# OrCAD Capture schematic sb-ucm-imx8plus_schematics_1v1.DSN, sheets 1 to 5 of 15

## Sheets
1 11. MIPI-CSI2 Connector, GMSL: size A2; title: SB-UCM-iMX8PLUS    11. MIPI-CSI2, GMSL Deserializer; rev: 1.1; note: 8000168001
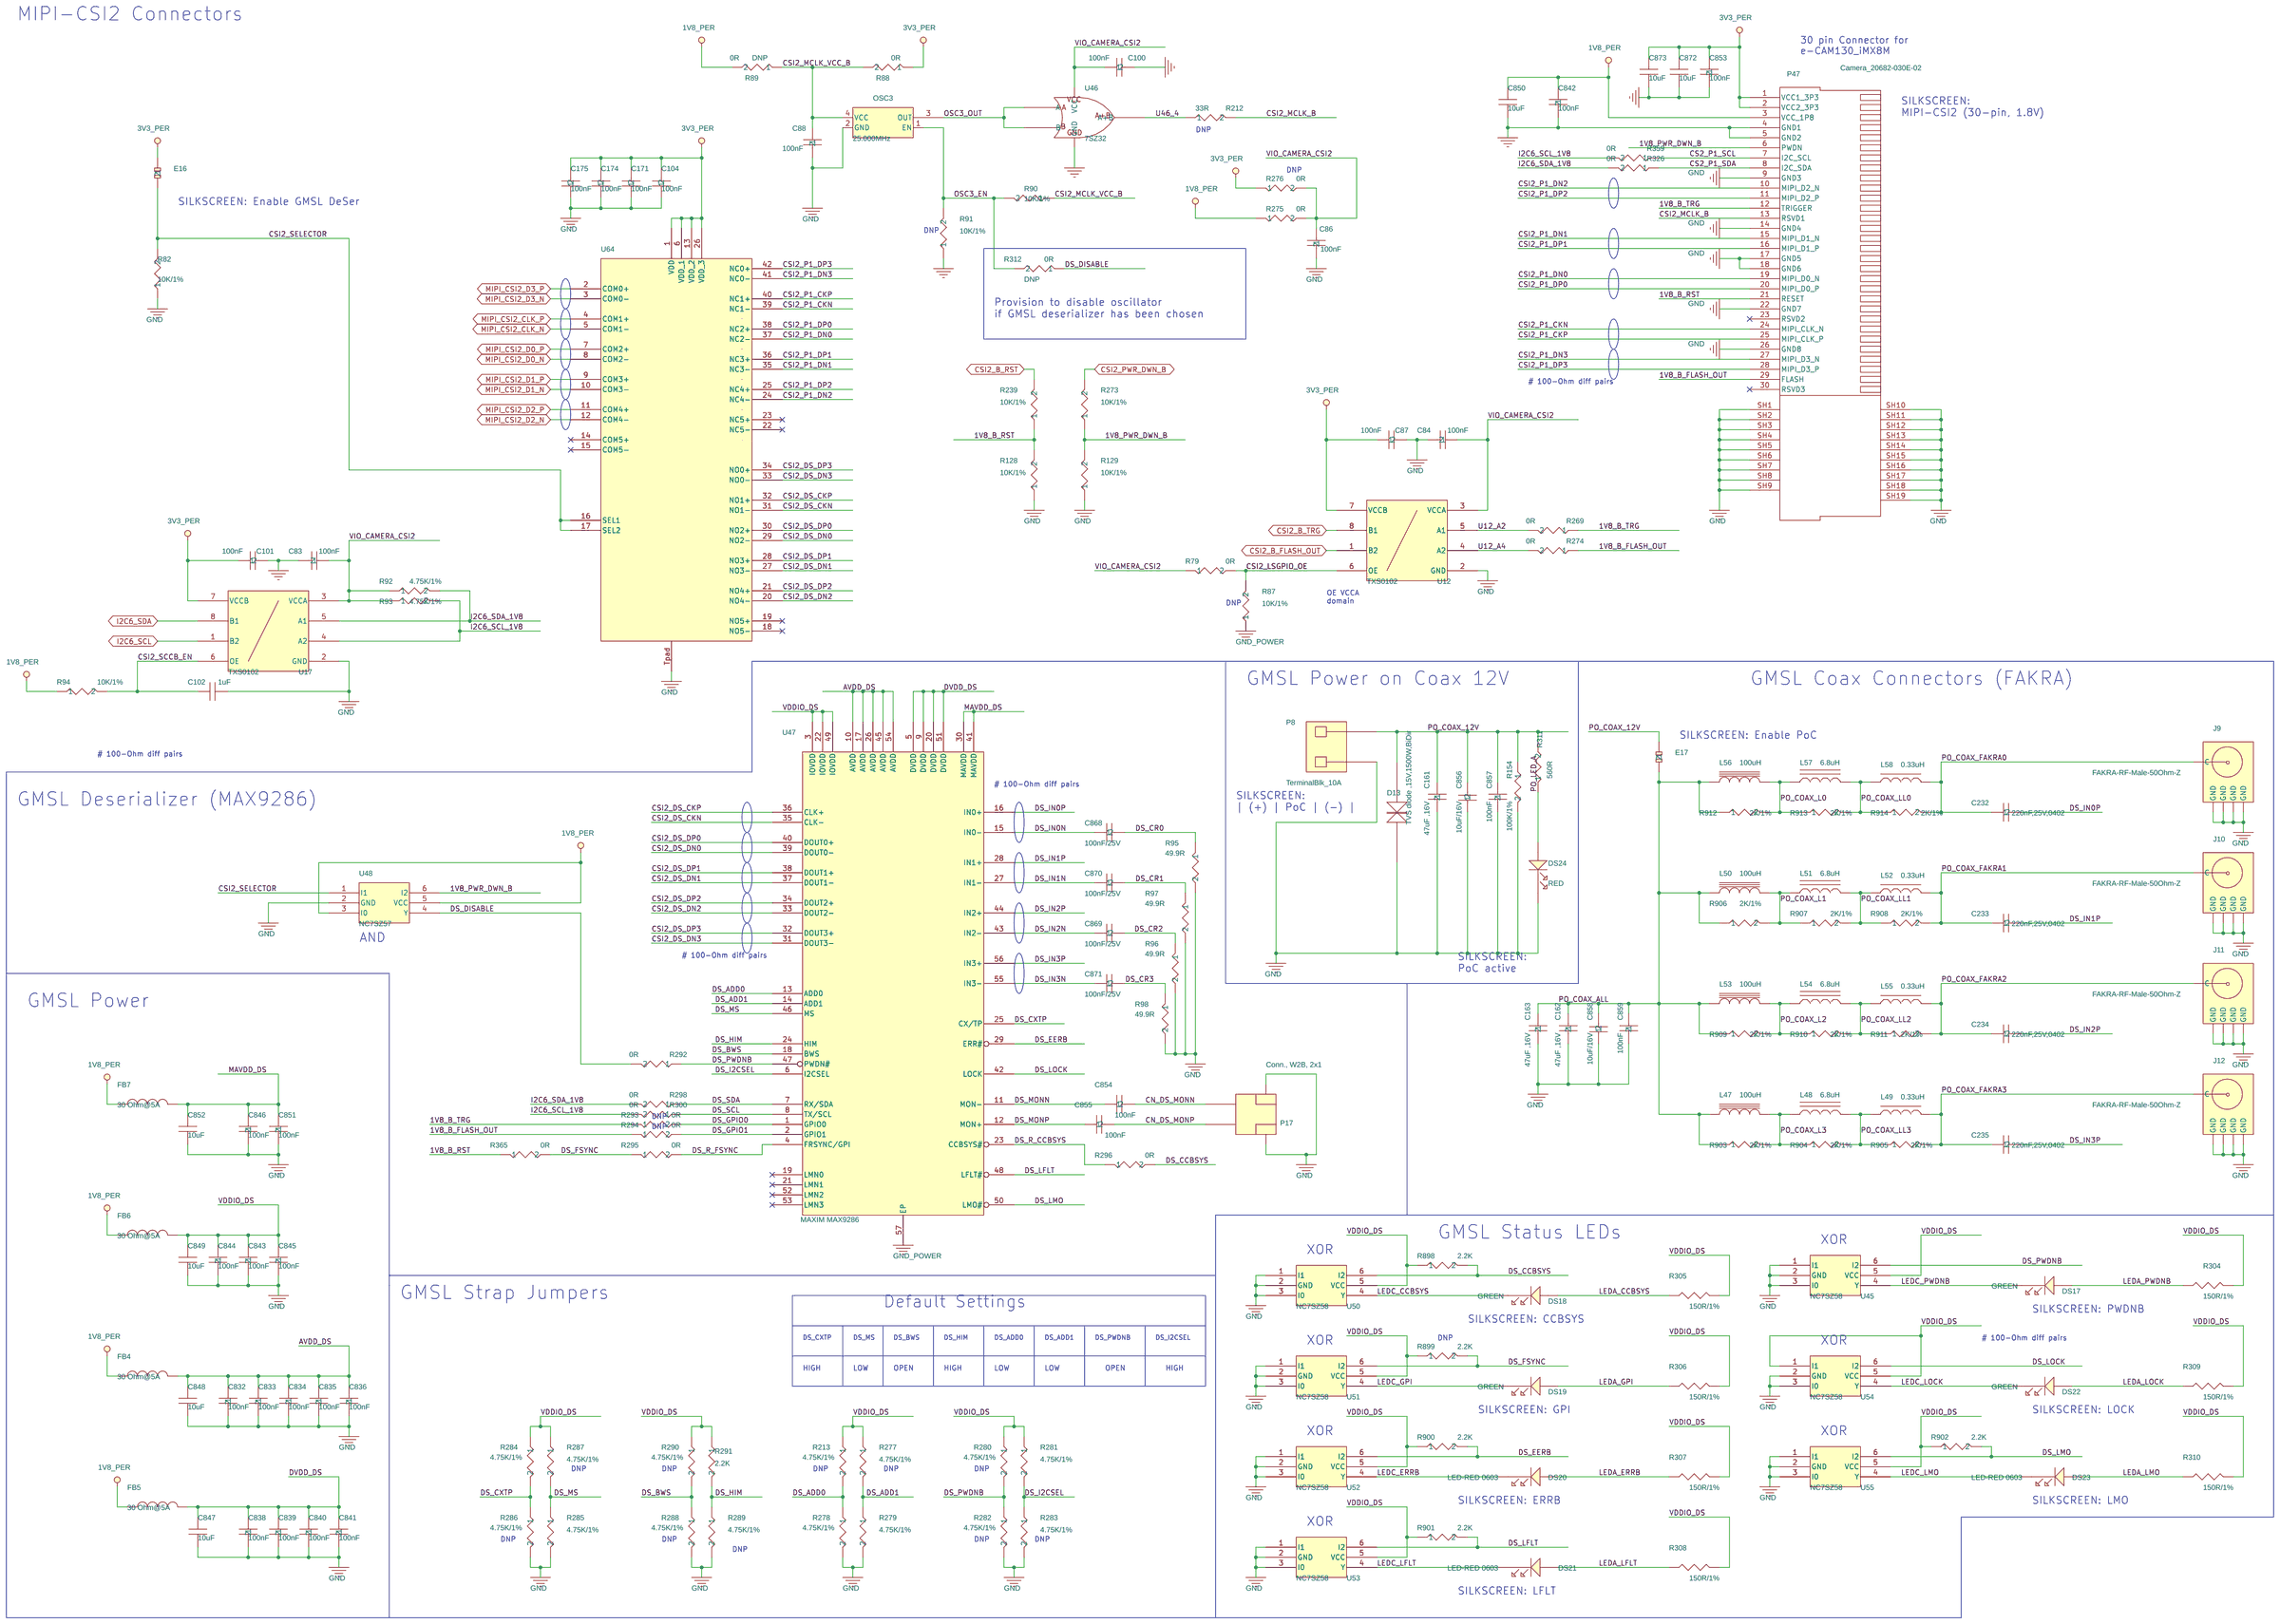
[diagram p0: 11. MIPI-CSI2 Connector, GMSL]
2 10. MIPI-CSI1 Connectors: size A3; title: SB-UCM-iMX8PLUS    10. MIPI-CSI1 Connectors
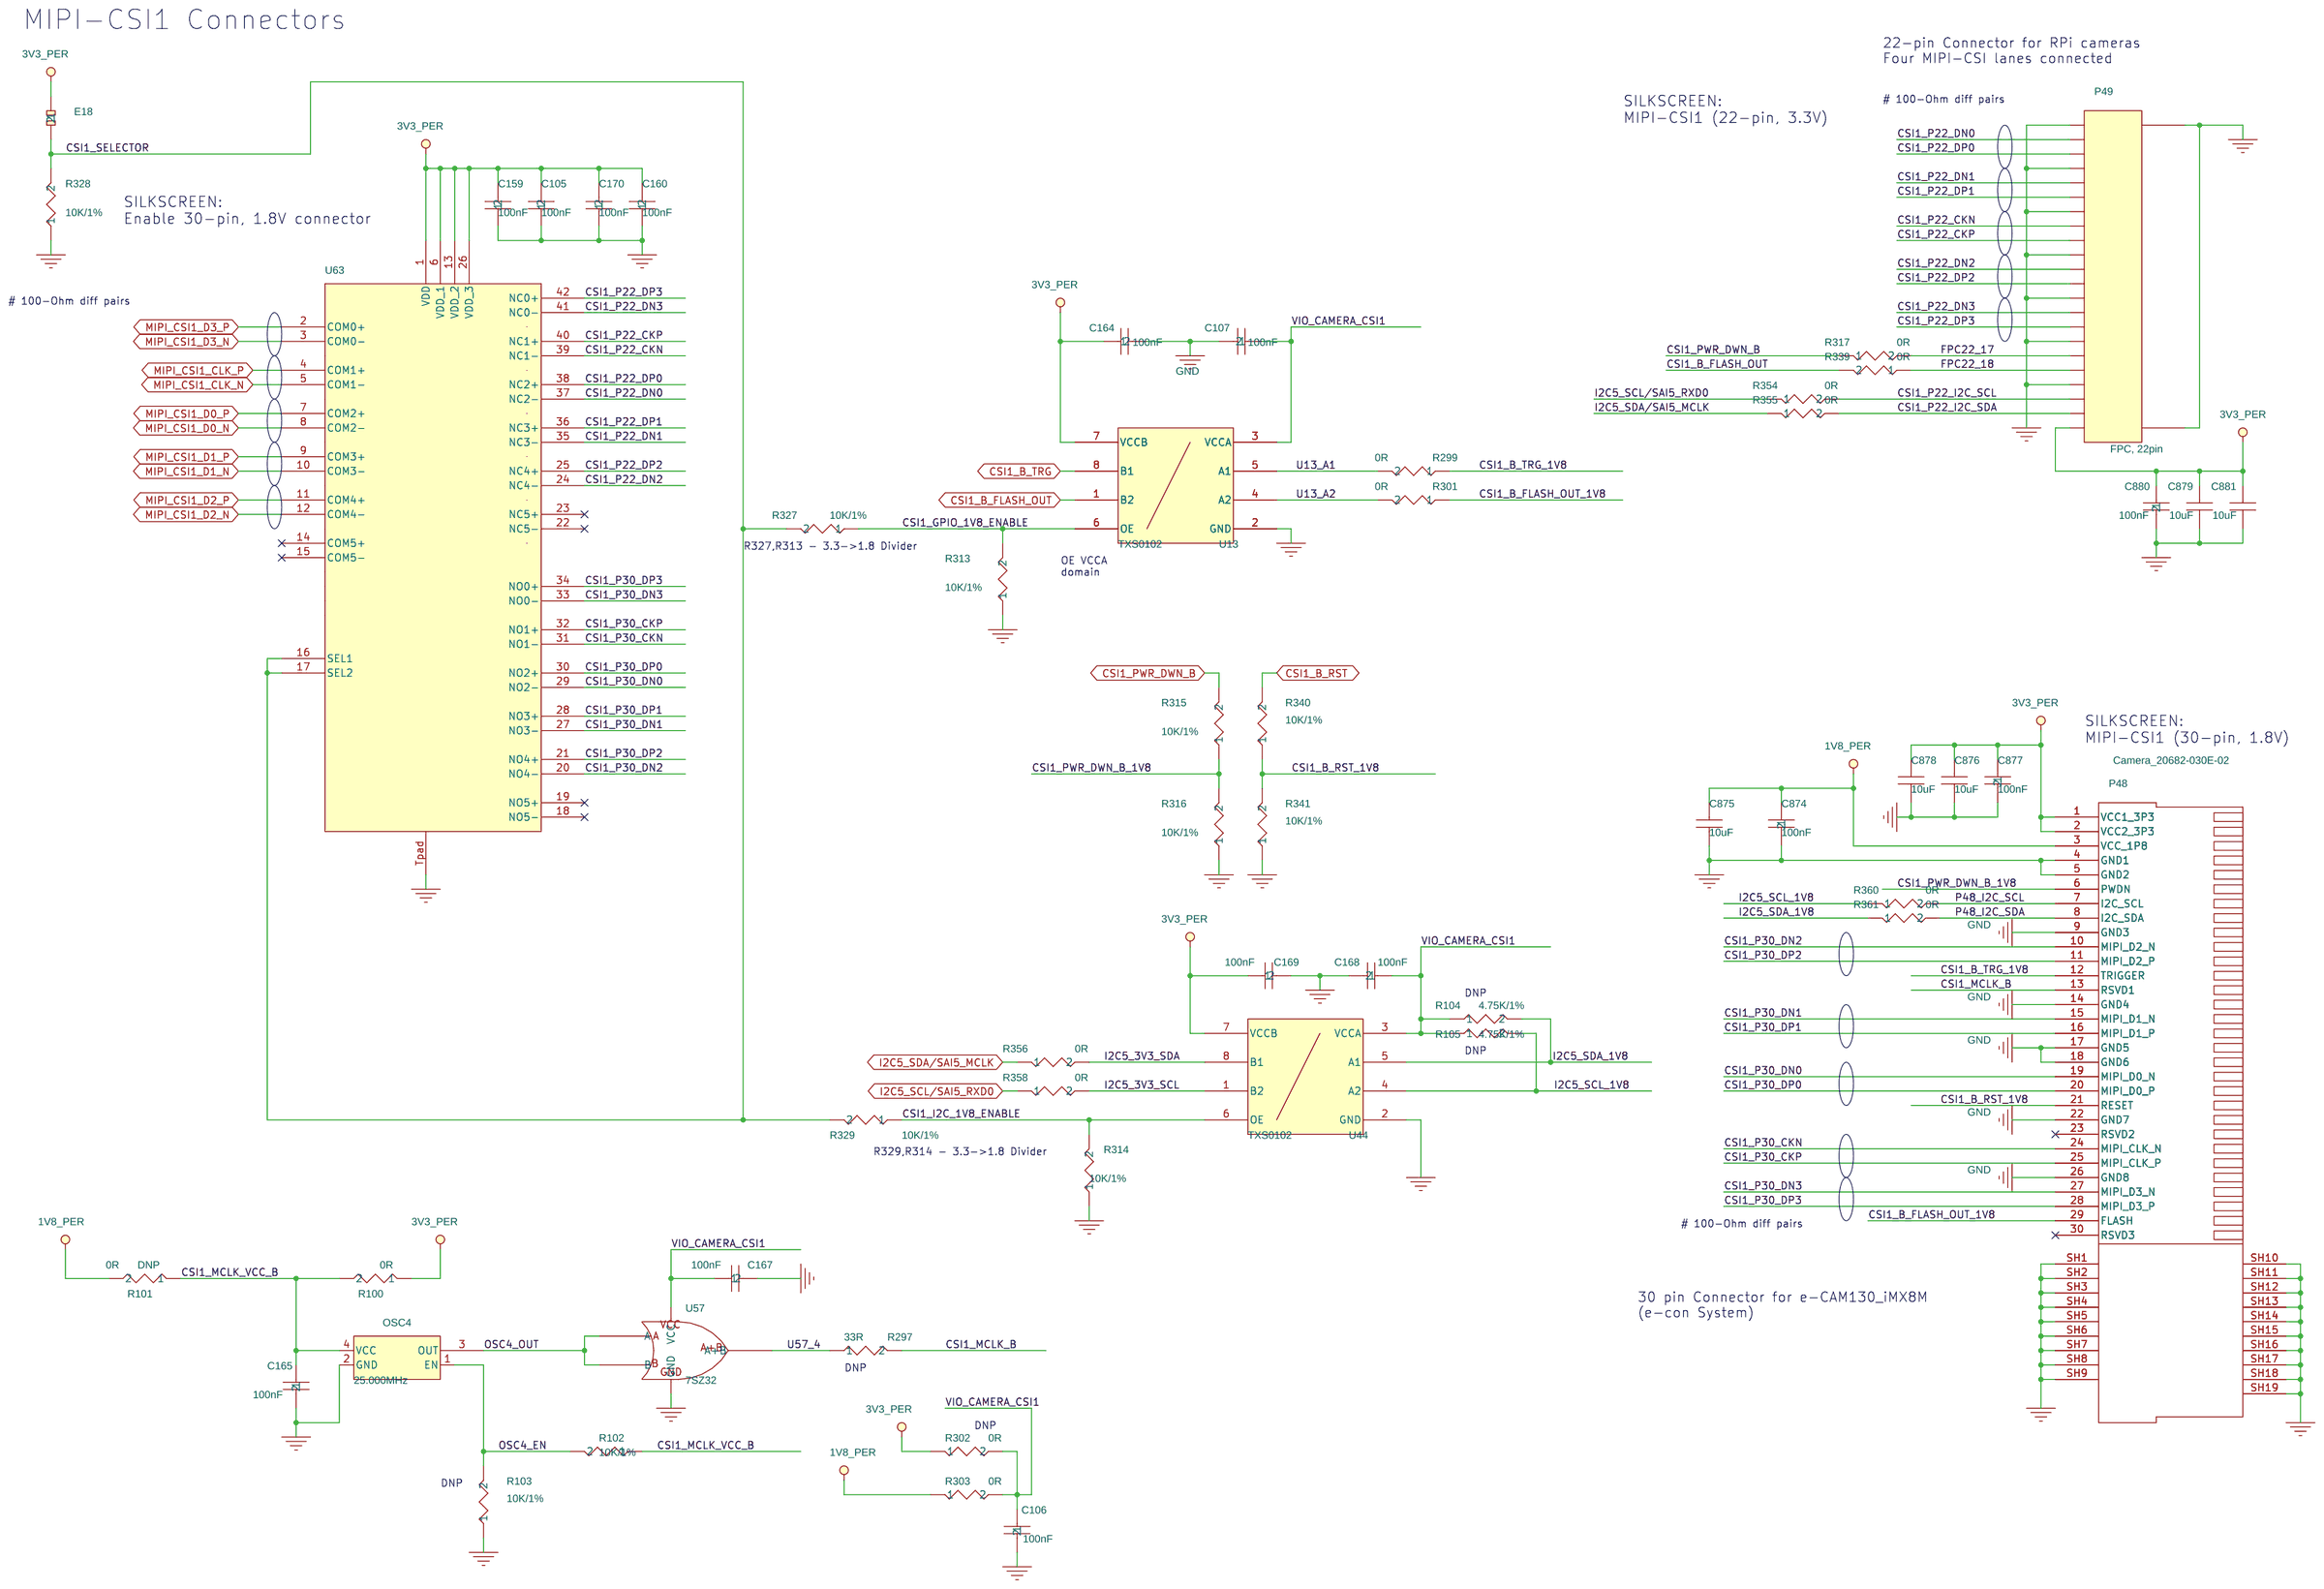
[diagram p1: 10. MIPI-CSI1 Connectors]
3 09. HDMI, eARC: size A3; title: SB-UCM-iMX8PLUS   09. HDMI, eARC
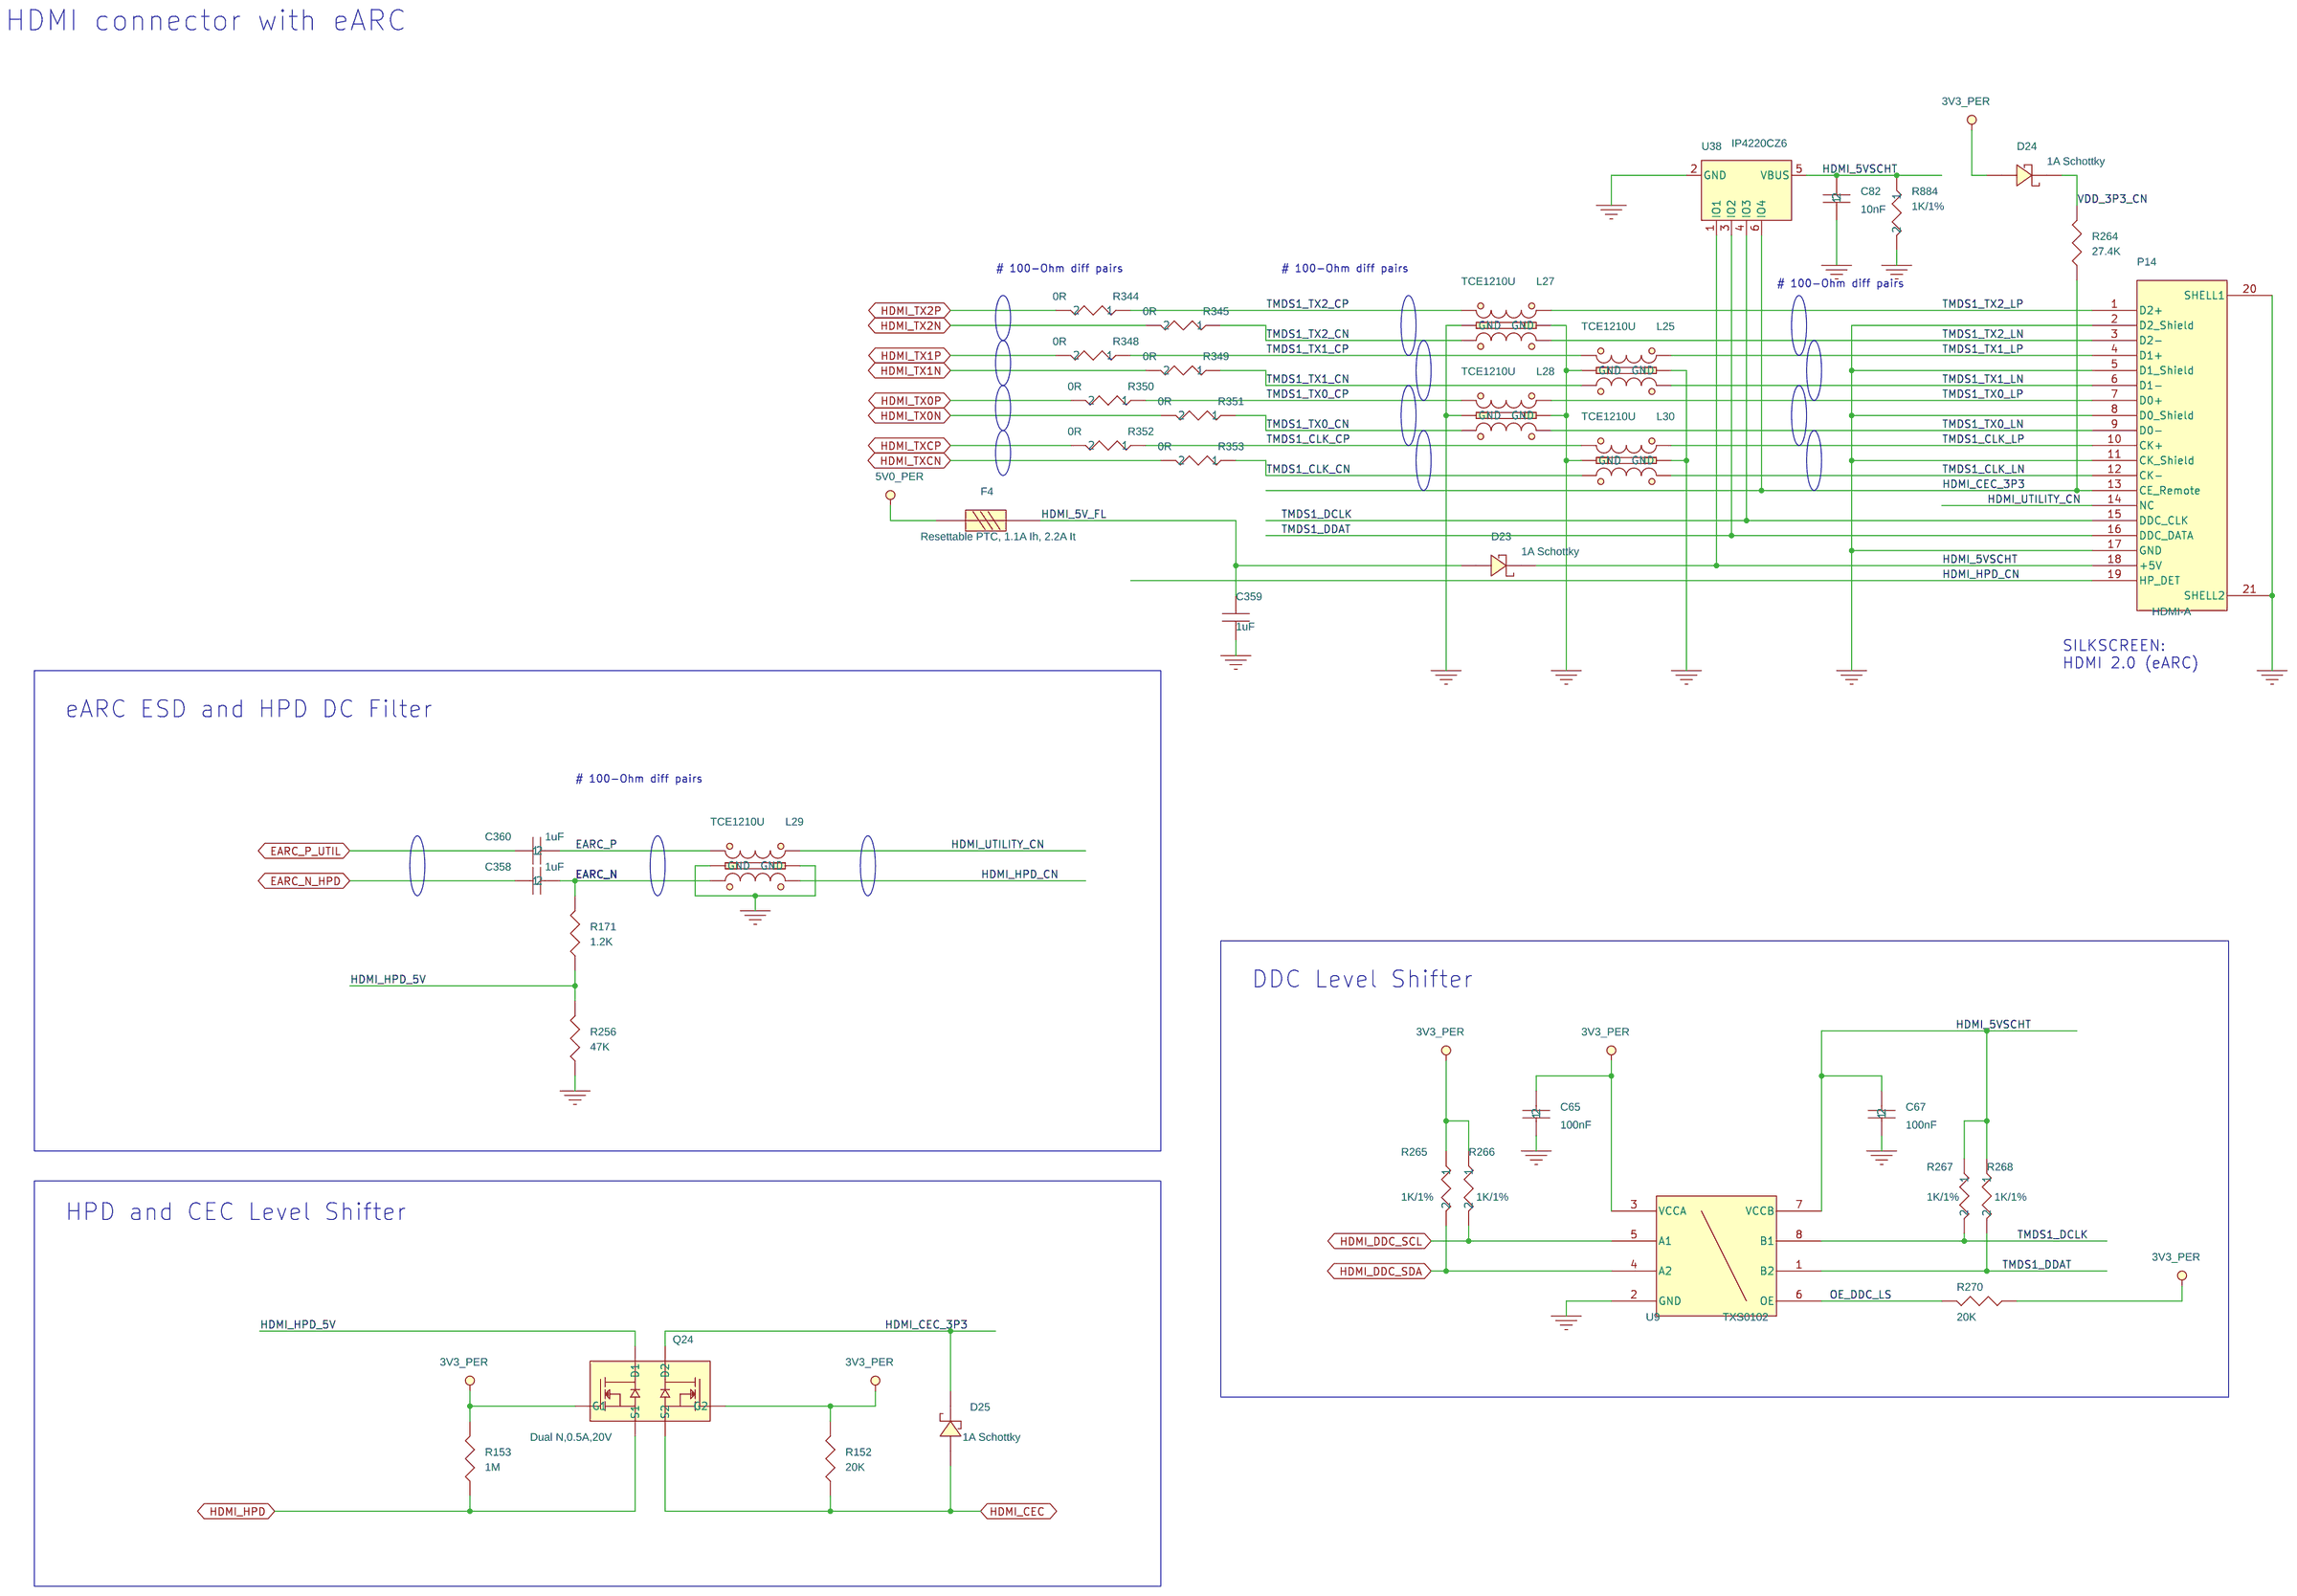
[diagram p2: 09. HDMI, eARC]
4 08. LVDS LCD: size A3; title: SB-UCM-iMX8PLUS   08. LVDS LCD
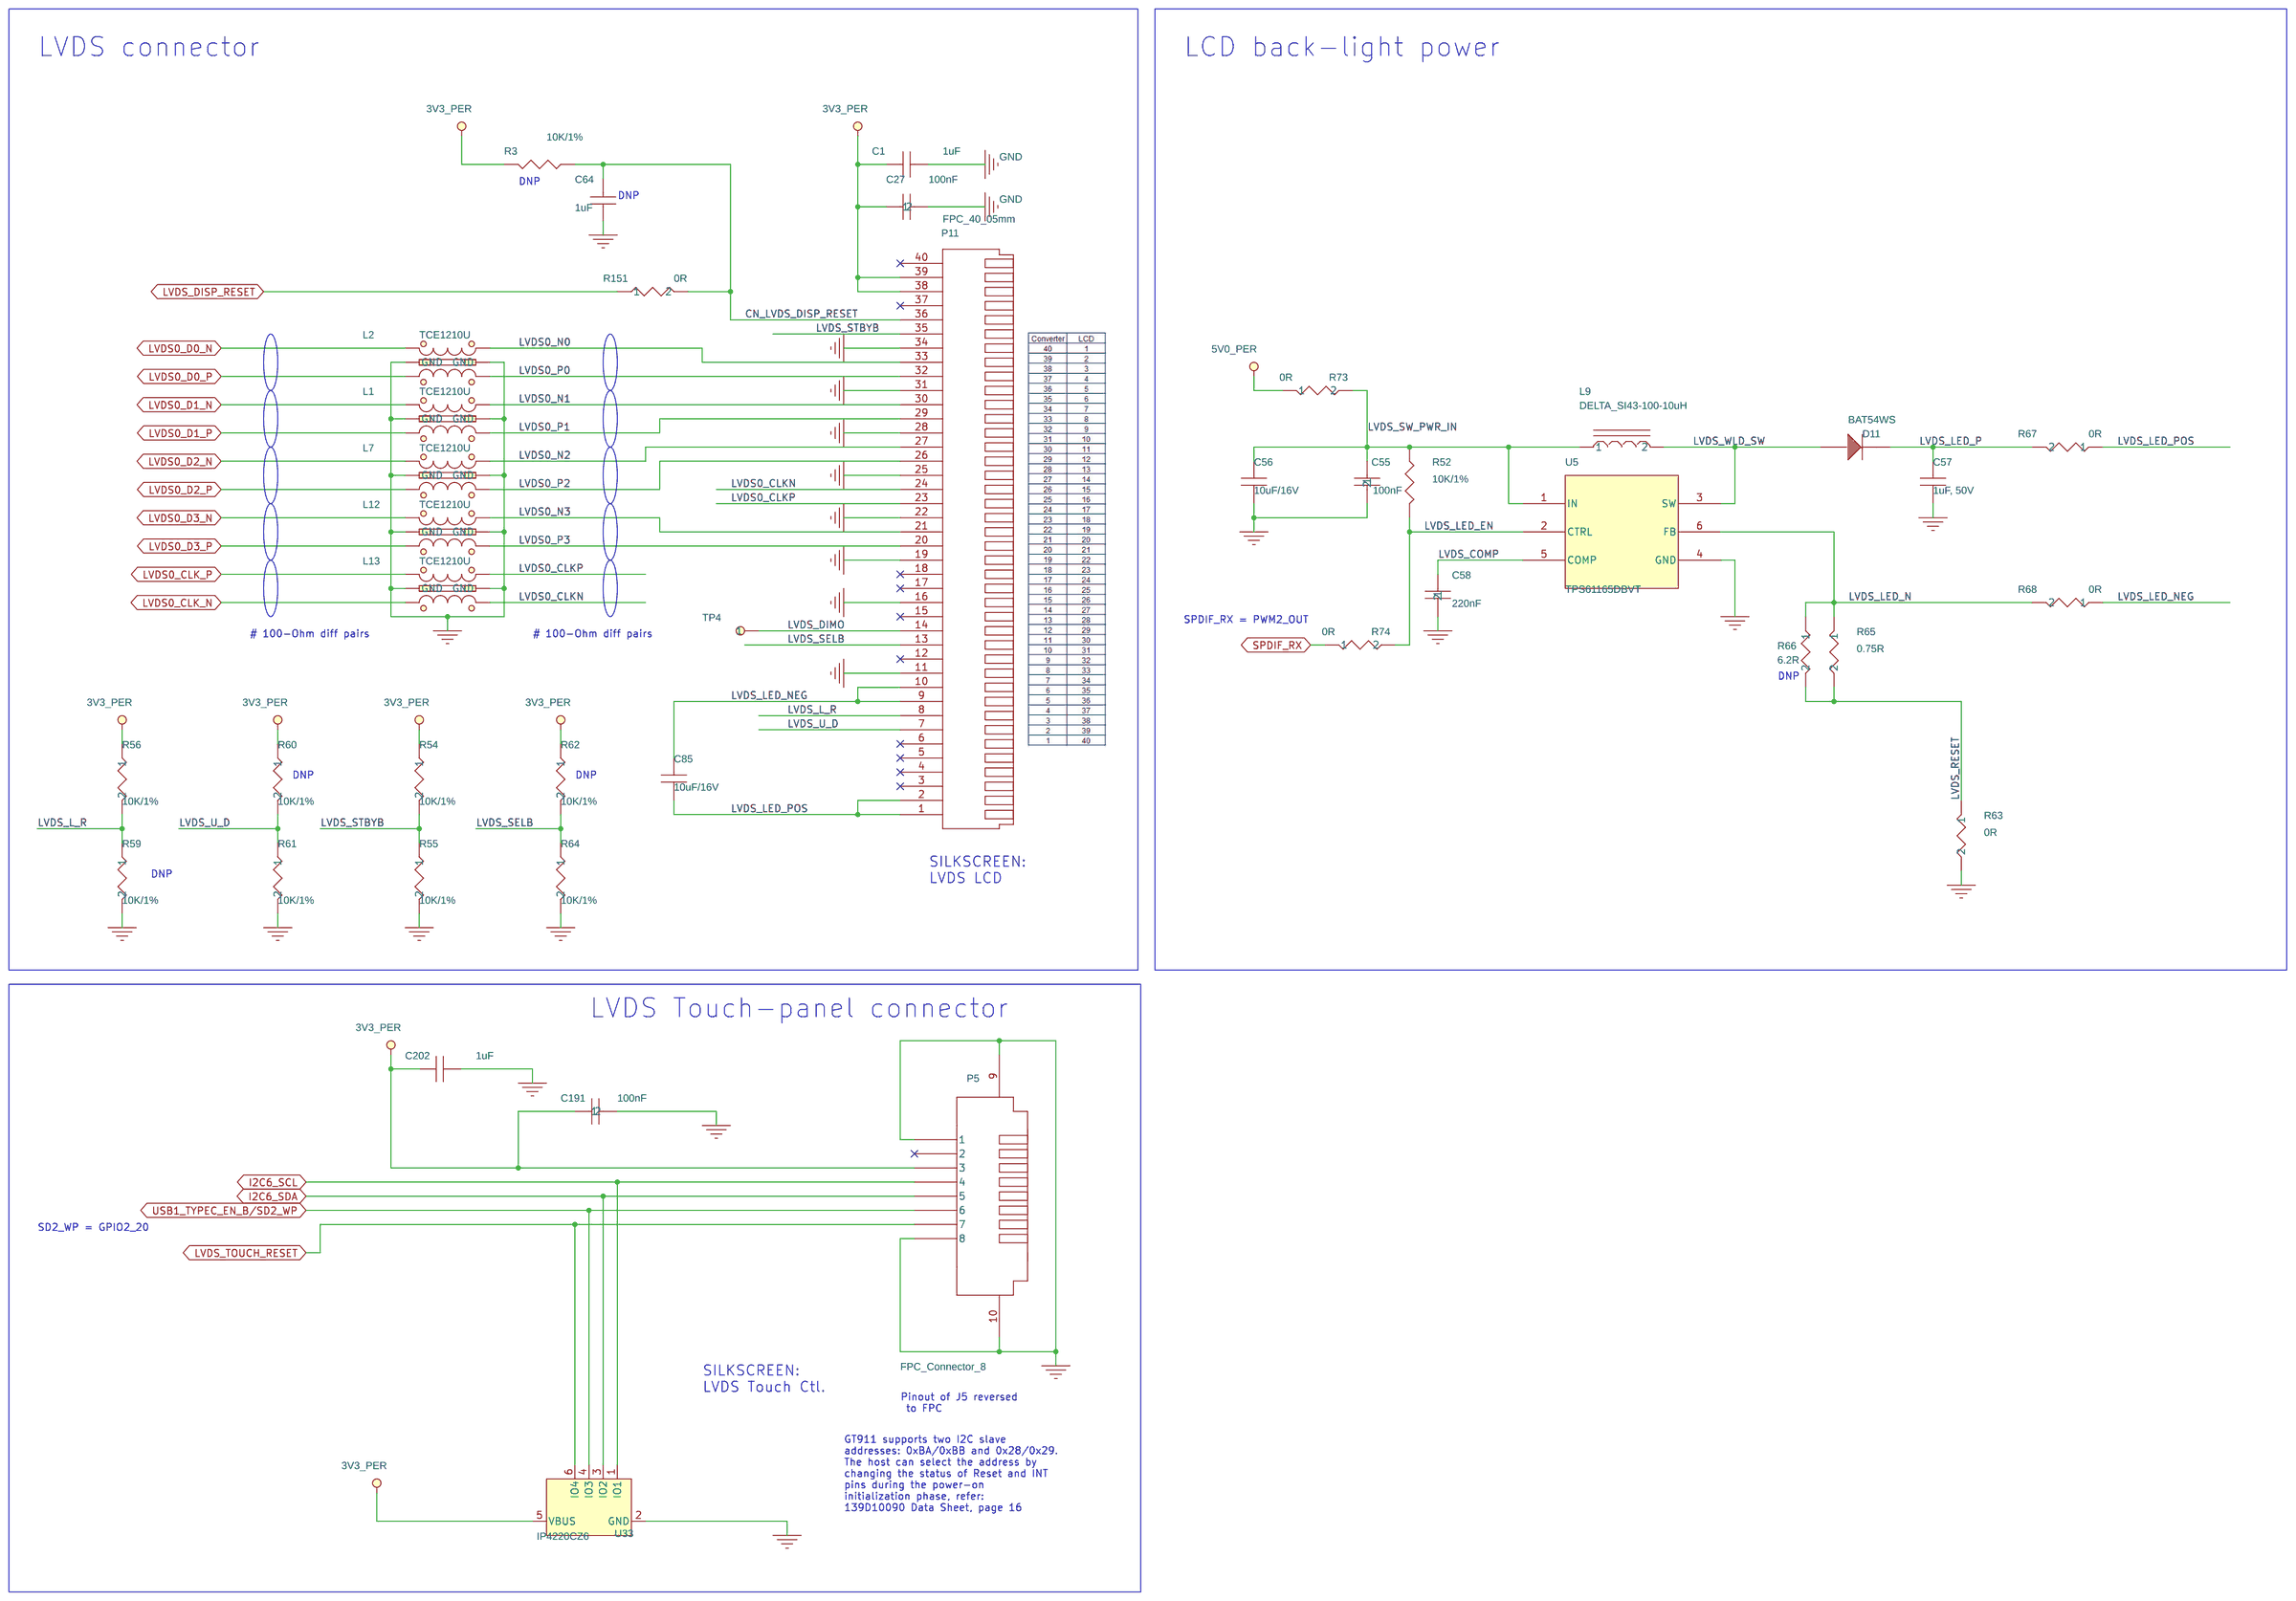
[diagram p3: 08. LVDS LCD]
5 01. Block Diagram: title: SB-UCM-iMX8PLUS   01. INDEX
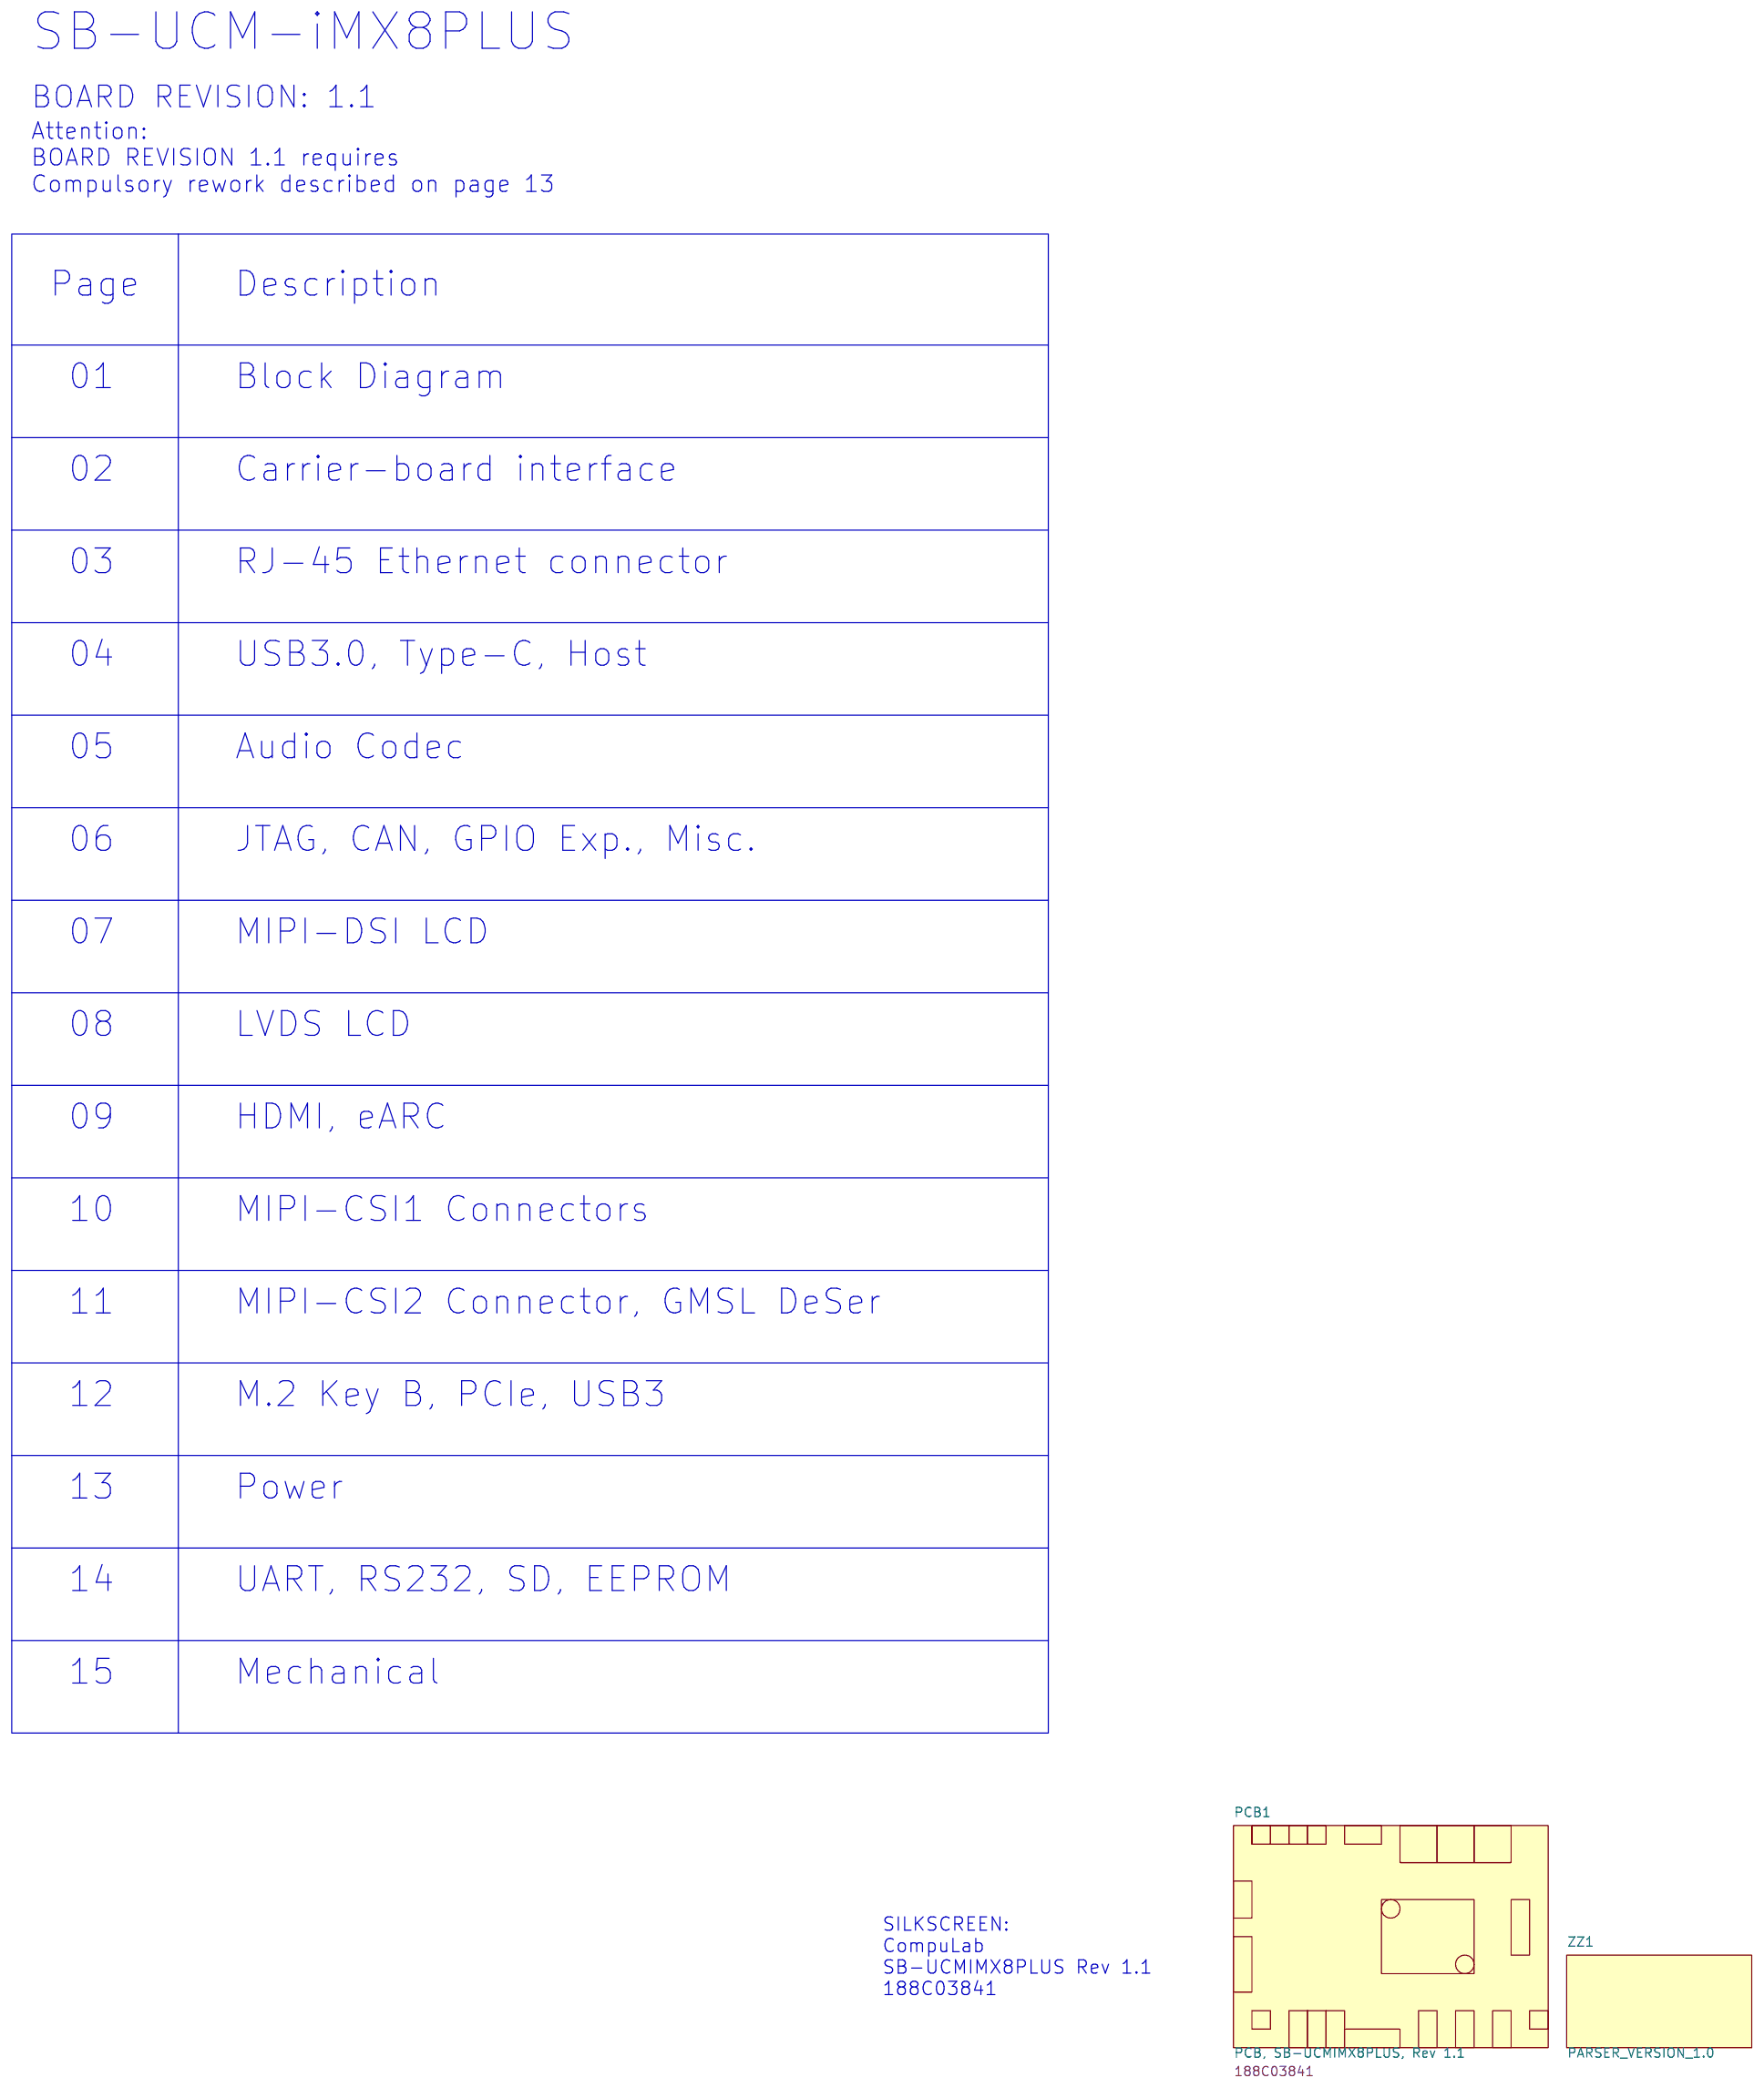
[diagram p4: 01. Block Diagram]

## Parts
sheet 01. Block Diagram
PCB1  PCB, SB-UCMIMX8PLUS, Rev 1.1
ZZ1  PARSER_VERSION_1.0
sheet 08. LVDS LCD
C1  1uF  [RC0402]
C27  100nF  [RC0402]
C55  100nF  [RC0402]
C56  10uF/16V  [RC0603]
C57  1uF, 50V  [RC0603]
C58  220nF  [RC0402]
C64  1uF  [RC0402]
C85  10uF/16V  [RC0603]
C191  100nF  [RC0402]
C202  1uF  [RC0402]
D11  BAT54WS  [SOD-323]
L1  TCE1210U  [EMI1012-ESD]
L2  TCE1210U  [EMI1012-ESD]
L7  TCE1210U  [EMI1012-ESD]
L9  DELTA_SI43-100-10uH  [IND4x4x2_5]
L12  TCE1210U  [EMI1012-ESD]
L13  TCE1210U  [EMI1012-ESD]
P5  FPC_Connector_8  [FPC_8]
P11  FPC_40_05mm  [FPC05SM40-1]
R3  10K/1%  [RC0402]
R52  10K/1%  [RC0402]
R54  10K/1%  [RC0402]
R55  10K/1%  [RC0402]
R56  10K/1%  [RC0402]
R59  10K/1%  [RC0402]
R60  10K/1%  [RC0402]
R61  10K/1%  [RC0402]
R62  10K/1%  [RC0402]
R63  0R  [RC0402]
R64  10K/1%  [RC0402]
R65  0.75R  [RC0402]
R66  6.2R  [RC0402]
R67  0R  [RC1206]
R68  0R  [RC1206]
R73  0R  [RC1206]
R74  0R  [RC1206]
R151  0R  [RC0402]
TP4  TESTPOINT  [TESTPOINT]
U5  TPS61165DBVT  [SOT23-6]
U33  IP4220CZ6  [SOT23-6L]
sheet 09. HDMI, eARC
C65  100nF  [RC0402]
C67  100nF  [RC0402]
C82  10nF  [RC0402]
C358  1uF  [RC0402]
C359  1uF  [RC0402]
C360  1uF  [RC0402]
D23  1A Schottky  [SOD-123]
D24  1A Schottky  [SOD-123]
D25  1A Schottky  [SOD-123]
F4  Resettable PTC, 1.1A Ih, 2.2A It  [FUSE-1206]
L25  TCE1210U  [EMI1012-ESD]
L27  TCE1210U  [EMI1012-ESD]
L28  TCE1210U  [EMI1012-ESD]
L29  TCE1210U  [EMI1012-ESD]
L30  TCE1210U  [EMI1012-ESD]
P14  HDMI-A  [SMT(HDMI-A)]
Q24  Dual N,0.5A,20V  [SOT-563-6]
R152  20K  [RC0402]
R153  1M  [RC0402]
R171  1.2K  [RC0402]
R256  47K  [RC0402]
R264  27.4K  [RC0402]
R265  1K/1%  [RC0402]
R266  1K/1%  [RC0402]
R267  1K/1%  [RC0402]
R268  1K/1%  [RC0402]
R270  20K  [RC0402]
R344  0R  [RC0402]
R345  0R  [RC0402]
R348  0R  [RC0402]
R349  0R  [RC0402]
R350  0R  [RC0402]
R351  0R  [RC0402]
R352  0R  [RC0402]
R353  0R  [RC0402]
R884  1K/1%  [RC0402]
U9  TXS0102  [MO-187DA-8]
U38  IP4220CZ6  [SOT23-6L]
sheet 10. MIPI-CSI1 Connectors
C105  100nF  [RC0402]
C106  100nF  [RC0402]
C107  100nF  [RC0402]
C159  100nF  [RC0402]
C160  100nF  [RC0402]
C164  100nF  [RC0402]
C165  100nF  [RC0402]
C167  100nF  [RC0402]
C168  100nF  [RC0402]
C169  100nF  [RC0402]
C170  100nF  [RC0402]
C874  100nF  [RC0402]
C875  10uF  [RC0603]
C876  10uF  [RC0603]
C877  100nF  [RC0402]
C878  10uF  [RC0603]
C879  10uF  [RC0603]
C880  100nF  [RC0402]
C881  10uF  [RC0603]
E18  HDR1X2  [1X2THHDR]
OSC4  25.000MHz  [OSC3225]
P48  Camera_20682-030E-02  [CON30]
P49  FPC, 22pin  [FPC05SM22]
R100  0R  [RC0402]
R101  0R  [RC0402]
R102  10K/1%  [RC0402]
R103  10K/1%  [RC0402]
R104  4.75K/1%  [RC0402]
R105  4.75K/1%  [RC0402]
R297  33R  [RC0402]
R299  0R  [RC0402]
R301  0R  [RC0402]
R302  0R  [RC0402]
R303  0R  [RC0402]
R313  10K/1%  [RC0402]
R314  10K/1%  [RC0402]
R315  10K/1%  [RC0402]
R316  10K/1%  [RC0402]
R317  0R  [RC0402]
R327  10K/1%  [RC0402]
R328  10K/1%  [RC0402]
R329  10K/1%  [RC0402]
R339  0R  [RC0402]
R340  10K/1%  [RC0402]
R341  10K/1%  [RC0402]
R354  0R  [RC0402]
R355  0R  [RC0402]
R356  0R  [RC0402]
R358  0R  [RC0402]
R360  0R  [RC0402]
R361  0R  [RC0402]
U13  TXS0102  [MO-187DA-8]
U44  TXS0102  [MO-187DA-8]
U57  7SZ32  [SC70]
U63  Value  [21-0181B_T423590M-1_MXM]
sheet 11. MIPI-CSI2 Connector, GMSL
C83  100nF  [RC0402]
C84  100nF  [RC0402]
C86  100nF  [RC0402]
C87  100nF  [RC0402]
C88  100nF  [RC0402]
C100  100nF  [RC0402]
C101  100nF  [RC0402]
C102  1uF  [RC0402]
C104  100nF  [RC0402]
C161  47uF ,16V  [C1210H2_5]
C162  47uF ,16V  [C1210H2_5]
C163  47uF ,16V  [C1210H2_5]
C171  100nF  [RC0402]
C174  100nF  [RC0402]
C175  100nF  [RC0402]
C232  220nF,25V,0402  [RC0402]
C233  220nF,25V,0402  [RC0402]
C234  220nF,25V,0402  [RC0402]
C235  220nF,25V,0402  [RC0402]
C832  100nF  [RC0402]
C833  100nF  [RC0402]
C834  100nF  [RC0402]
C835  100nF  [RC0402]
C836  100nF  [RC0402]
C838  100nF  [RC0402]
C839  100nF  [RC0402]
C840  100nF  [RC0402]
C841  100nF  [RC0402]
C842  100nF  [RC0402]
C843  100nF  [RC0402]
C844  100nF  [RC0402]
C845  100nF  [RC0402]
C846  100nF  [RC0402]
C847  10uF  [RC0603]
C848  10uF  [RC0603]
C849  10uF  [RC0603]
C850  10uF  [RC0603]
C851  100nF  [RC0402]
C852  10uF  [RC0603]
C853  100nF  [RC0402]
C854  100nF  [RC0402]
C855  100nF  [RC0402]
C856  10uF/16V  [RC0603]
C857  100nF  [RC0402]
C858  10uF/16V  [RC0603]
C859  100nF  [RC0402]
C868  100nF/25V  [RC0402]
C869  100nF/25V  [RC0402]
C870  100nF/25V  [RC0402]
C871  100nF/25V  [RC0402]
C872  10uF  [RC0603]
C873  10uF  [RC0603]
D13  TVS diode ,15V,1500W,BiDir  [DO-214AB]
DS17  GREEN  [LED-0603]
DS18  GREEN  [LED-0603]
DS19  GREEN  [LED-0603]
DS20  LED-RED 0603  [LED-0603]
DS21  LED-RED 0603  [LED-0603]
DS22  GREEN  [LED-0603]
DS23  LED-RED 0603  [LED-0603]
DS24  RED  [LED-1206]
E16  HDR1X2  [1X2THHDR]
E17  HDR1X2  [1X2THHDR]
FB4  30 Ohm@5A  [FB0603]
FB5  30 Ohm@5A  [FB0603]
FB6  30 Ohm@5A  [FB0603]
FB7  30 Ohm@5A  [FB0603]
J9  FAKRA-RF-Male-50Ohm-Z  [SMB-JACK]
J10  FAKRA-RF-Male-50Ohm-Z  [SMB-JACK]
J11  FAKRA-RF-Male-50Ohm-Z  [SMB-JACK]
J12  FAKRA-RF-Male-50Ohm-Z  [SMB-JACK]
L47  100uH  [IND9x9x4_5]
L48  6.8uH  [IND8_2x8_2]
L49  0.33uH  [FB0603]
L50  100uH  [IND9x9x4_5]
L51  6.8uH  [IND8_2x8_2]
L52  0.33uH  [FB0603]
L53  100uH  [IND9x9x4_5]
L54  6.8uH  [IND8_2x8_2]
L55  0.33uH  [FB0603]
L56  100uH  [IND9x9x4_5]
L57  6.8uH  [IND8_2x8_2]
L58  0.33uH  [FB0603]
OSC3  25.000MHz  [OSC3225]
P8  TerminalBlk_10A  [TB3.5mmRA-2P]
P17  Conn., W2B, 2x1  [1x2W2B1_25RASM]
P47  Camera_20682-030E-02  [CON30]
R79  0R  [RC0402]
R82  10K/1%  [RC0402]
R87  10K/1%  [RC0402]
R88  0R  [RC0402]
R89  0R  [RC0402]
R90  10K/1%  [RC0402]
R91  10K/1%  [RC0402]
R92  4.75K/1%  [RC0402]
R93  4.75K/1%  [RC0402]
R94  10K/1%  [RC0402]
R95  49.9R  [RC0402]
R96  49.9R  [RC0402]
R97  49.9R  [RC0402]
R98  49.9R  [RC0402]
R128  10K/1%  [RC0402]
R129  10K/1%  [RC0402]
R154  100K/1%  [RC0402]
R212  33R  [RC0402]
R213  4.75K/1%  [RC0402]
R239  10K/1%  [RC0402]
R269  0R  [RC0402]
R273  10K/1%  [RC0402]
R274  0R  [RC0402]
R275  0R  [RC0402]
R276  0R  [RC0402]
R277  4.75K/1%  [RC0402]
R278  4.75K/1%  [RC0402]
R279  4.75K/1%  [RC0402]
R280  4.75K/1%  [RC0402]
R281  4.75K/1%  [RC0402]
R282  4.75K/1%  [RC0402]
R283  4.75K/1%  [RC0402]
R284  4.75K/1%  [RC0402]
R285  4.75K/1%  [RC0402]
R286  4.75K/1%  [RC0402]
R287  4.75K/1%  [RC0402]
R288  4.75K/1%  [RC0402]
R289  4.75K/1%  [RC0402]
R290  4.75K/1%  [RC0402]
R291  2.2K
R292  0R  [RC0402]
R293  0R  [RC0402]
R294  0R  [RC0402]
R295  0R  [RC0402]
R296  0R  [RC0402]
R298  0R  [RC0402]
R300  0R  [RC0402]
R304  150R/1%  [RC0402]
R305  150R/1%  [RC0402]
R306  150R/1%  [RC0402]
R307  150R/1%  [RC0402]
R308  150R/1%  [RC0402]
R309  150R/1%  [RC0402]
R310  150R/1%  [RC0402]
R311  560R  [RC00603]
R312  0R  [RC0402]
R326  0R  [RC0402]
R359  0R  [RC0402]
R365  0R  [RC0402]
R898  2.2K  [RC0402]
R899  2.2K  [RC0402]
R900  2.2K  [RC0402]
R901  2.2K  [RC0402]
R902  2.2K  [RC0402]
R903  2K/1%  [RC0402]
R904  2K/1%  [RC0402]
R905  2K/1%  [RC0402]
R906  2K/1%  [RC0402]
R907  2K/1%  [RC0402]
R908  2K/1%  [RC0402]
R909  2K/1%  [RC0402]
R910  2K/1%  [RC0402]
R911  2K/1%  [RC0402]
R912  2K/1%  [RC0402]
R913  2K/1%  [RC0402]
R914  2K/1%  [RC0402]
U12  TXS0102  [MO-187DA-8]
U17  TXS0102  [MO-187DA-8]
U45  NC7SZ58  [MO-252UAAD]
U46  7SZ32  [SC70]
U47  MAXIM MAX9286  [MO-220WLLD-5]
U48  NC7SZ57  [MO-252UAAD]
U50  NC7SZ58  [MO-252UAAD]
U51  NC7SZ58  [MO-252UAAD]
U52  NC7SZ58  [MO-252UAAD]
U53  NC7SZ58  [MO-252UAAD]
U54  NC7SZ58  [MO-252UAAD]
U55  NC7SZ58  [MO-252UAAD]
U64  Value  [21-0181B_T423590M-1_MXM]

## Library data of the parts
PCB1 = PCB,_EM-X270_Rev_1_5.1: CLABCONF0: =SB-UCMIMX8PLUS; P/N: 188C03841
ZZ1 = PARSER_VERSION_1_1.0: CLABCONF0: DNP
C1 C102 C202 = 1uF,X5R,6.3V,0402: CLABCONF0: =SB-UCMIMX8PLUS
C27 C840 C874 = 100nF,_10V,_X7R,_10%,_0402: CLABCONF0: =SB-UCMIMX8PLUS
C55 C67 C168 C841 = 100nF,_10V,_X7R,_10%,_0402_3: CLABCONF0: =SB-UCMIMX8PLUS
C56 = 10uF,6.3V,0603,20%X5R_1: CLABCONF0: =SB-UCMIMX8PLUS
C57 = 1uF,X5R,6.3V,0402: CLABCONF0: =SB-UCMIMX8PLUS; P/N: 151D10510S
C58 = 100nF,_10V,_X7R,_10%,_0402_2: CLABCONF0: =SB-UCMIMX8PLUS; P/N: 151C22400S
C64 = 1uF,X5R,6.3V,0402: CLABCONF0: DNP
C85 = 10uF,6.3V,0603,20%X5R: CLABCONF0: =SB-UCMIMX8PLUS
C170 C191 C846 = 100nF,_10V,_X7R,_10%,_0402_1: CLABCONF0: =SB-UCMIMX8PLUS
D11 = BAT54WS_0: CLABCONF0: =SB-UCMIMX8PLUS
L1 L2 L7 L12 L13 L25 L27-L30 = ESD_CHOKE_DIFFx2_10: CLABCONF0: =SB-UCMIMX8PLUS; P/N: 142D11801S
L9 = INC_DELTA_SI43-100,_10uH: CLABCONF0: =SB-UCMIMX8PLUS; CLABCONF1: <null>
P5 = FPC_Connector_6: CLABCONF0: =SB-UCMIMX8PLUS; P/N: 182P00803S
P11 = FPC_40_05mm: CLABCONF0: =SB-UCMIMX8PLUS; P/N: 182P04001S
R3 = 10K,1%,0402,1_16W_0_1: CLABCONF0: DNP
R52 = 10K,1%,0402,1_16W_0: CLABCONF0: =SB-UCMIMX8PLUS
R54 R128 R328 = 10K,1%,0402,1_16W_3: CLABCONF0: =SB-UCMIMX8PLUS
R55 = 10K,1%,0402,1_16W_5: CLABCONF0: DNP
R56 R239 R327 = 10K,1%,0402,1_16W_6: CLABCONF0: =SB-UCMIMX8PLUS
R59 = 10K,1%,0402,1_16W_7: CLABCONF0: DNP
R60 R87 R103 = 10K,1%,0402,1_16W: CLABCONF0: DNP
R61 R82 R340 = 10K,1%,0402,1_16W_1: CLABCONF0: =SB-UCMIMX8PLUS
R62 = 10K,1%,0402,1_16W_2: CLABCONF0: DNP
R63 = 2.2R,5%,0402,1_16W_1: CLABCONF0: =SB-UCMIMX8PLUS; P/N: 161C00005S
R64 R341 = 10K,1%,0402,1_16W_4: CLABCONF0: =SB-UCMIMX8PLUS
R65 = 2.2R,5%,0402,1_16W_2: CLABCONF0: =SB-UCMIMX8PLUS; P/N: 161C0R751S
R66 = 2.2R,5%,0402,1_16W: CLABCONF0: DNP; P/N: 161C06R25S
R67 = 0R,_1206: CLABCONF0: =SB-UCMIMX8PLUS
R68 = 0R,_1206_1: CLABCONF0: =SB-UCMIMX8PLUS
R73 = 0R,_1206_2: CLABCONF0: =SB-UCMIMX8PLUS
R74 = 0R,_1206_3: CLABCONF0: =SB-UCMIMX8PLUS
R151 = 0R,_0402: CLABCONF0: =SB-UCMIMX8PLUS
TP4 = TESTPOINT: CLABCONF0: DNP
U5 = TPS61165DBVT: CLABCONF0: =SB-UCMIMX8PLUS; P/N: 123C15100S
U33 U38 = IP4220CZ6_0: CLABCONF0: =SB-UCMIMX8PLUS
C65 C159 C174 = 100nF,_10V,_X7R,_10%,_0402_2: CLABCONF0: =SB-UCMIMX8PLUS
C82 = 10nF,_25V,_X7R,_10%,_0402: CLABCONF0: =SB-UCMIMX8PLUS
C358 = 100nF,_10V,_X7R,_10%,_0402: CLABCONF0: =SB-UCMIMX8PLUS; P/N: 151C10500S
C359 = Cap_1uF,X5R,6.3V,0402: CLABCONF0: =SB-UCMIMX8PLUS
C360 = 100nF,_10V,_X7R,_10%,_0402_1: CLABCONF0: =SB-UCMIMX8PLUS; P/N: 151C10500S
D23-D25 = 1A_Schottky_Barrier_Rectifier: CLABCONF0: =SB-UCMIMX8PLUS
F4 = Fuse,_0.75A_Ih,_1.5A_It: CLABCONF0: =SB-UCMIMX8PLUS; P/N: 175P22200S
P14 = HDMI_Connector: CLABCONF0: =SB-UCMIMX8PLUS
Q24 = DUAL_N-MOSFET,_0.5A_20V: CLABCONF0: =SB-UCMIMX8PLUS
R152 R270 = RESISTOR: CLABCONF0: =SB-UCMIMX8PLUS; P/N: 161C20021S
R153 = RESISTOR: CLABCONF0: =SB-UCMIMX8PLUS; P/N: 161C10045S
R171 = RESISTOR: CLABCONF0: =SB-UCMIMX8PLUS; P/N: 161C12011S
R256 = RESISTOR: CLABCONF0: =SB-UCMIMX8PLUS; P/N: 161C47025S
R264 = RESISTOR: CLABCONF0: =SB-UCMIMX8PLUS; P/N: 161C27421S
R265 = 1K,1%,0402,1_16W: CLABCONF0: =SB-UCMIMX8PLUS
R266 = 1K,1%,0402,1_16W_2: CLABCONF0: =SB-UCMIMX8PLUS
R267 = 1K,1%,0402,1_16W_3: CLABCONF0: =SB-UCMIMX8PLUS
R268 = 1K,1%,0402,1_16W_4: CLABCONF0: =SB-UCMIMX8PLUS
R269 R299 R344 = 0R,_0402_1_4: CLABCONF0: =SB-UCMIMX8PLUS
R274 R301 R345 = 0R,_0402_1_2: CLABCONF0: =SB-UCMIMX8PLUS
R348 = 0R,_0402_1_6: CLABCONF0: =SB-UCMIMX8PLUS
R349 = 0R,_0402_1_7: CLABCONF0: =SB-UCMIMX8PLUS
R100 R295 R350 = 0R,_0402_1: CLABCONF0: =SB-UCMIMX8PLUS
R339 R351 = 0R,_0402_1_1: CLABCONF0: =SB-UCMIMX8PLUS
R352 R365 = 0R,_0402_1_3: CLABCONF0: =SB-UCMIMX8PLUS
R88 R353 = 0R,_0402_1_5: CLABCONF0: =SB-UCMIMX8PLUS
R884 = 1K,1%,0402,1_16W_1: CLABCONF0: =SB-UCMIMX8PLUS
U9 U12 U13 U17 U44 = TXS0102_0: CLABCONF0: =SB-UCMIMX8PLUS; P/N: 116A01020S
C105 C175 = 100nF,_10V,_X7R,_10%,_0402_4: CLABCONF0: =SB-UCMIMX8PLUS
C106 C842 = 100nF,_10V,_X7R,_10%,_0402_11: CLABCONF0: =SB-UCMIMX8PLUS
C107 C851 = 100nF,_10V,_X7R,_10%,_0402_7: CLABCONF0: =SB-UCMIMX8PLUS
C160 C844 = 100nF,_10V,_X7R,_10%,_0402_12: CLABCONF0: =SB-UCMIMX8PLUS
C164 C857 = 100nF,_10V,_X7R,_10%,_0402_10: CLABCONF0: =SB-UCMIMX8PLUS
C165 C833 = 100nF,_10V,_X7R,_10%,_0402_8: CLABCONF0: =SB-UCMIMX8PLUS
C101 C167 = 100nF,_10V,_X7R,_10%,_0402_5: CLABCONF0: =SB-UCMIMX8PLUS
C169 C843 = 100nF,_10V,_X7R,_10%,_0402_9: CLABCONF0: =SB-UCMIMX8PLUS
C847-C850 C852 C872 C873 C875 C876 C878 C879 C881 = 10uF,6_0.3V,0603,20%X5R: CLABCONF0: =SB-UCMIMX8PLUS
C832 C877 = 100nF,_10V,_X7R,_10%,_0402_6: CLABCONF0: =SB-UCMIMX8PLUS
C83 C880 = 100nF,_10V,_X7R,_10%,_0402_13: CLABCONF0: =SB-UCMIMX8PLUS
E17 E18 = HDR_1x2_100MIL_TH_JUMPER: CLABCONF0: =SB-UCMIMX8PLUS
OSC3 OSC4 = Osc.,_50Mhz,50PPM,_3.3V: CLABCONF0: =SB-UCMIMX8PLUS; P/N: 141C25601S
P47 P48 = Camera_20682-030E-02: CLABCONF0: =SB-UCMIMX8PLUS; P/N: 182K03002S
P49 = FPC,_0.5mm,_22_cont_0.: CLABCONF0: =SB-UCMIMX8PLUS; P/N: 182P02201S
R101 = 0R,_0402_1_3: CLABCONF0: DNP
R102 R273 = 10K,1%,0402,1_16W_8: CLABCONF0: =SB-UCMIMX8PLUS
R104 = 4_0.75K,1%,0402,1_16W: CLABCONF0: DNP
R105 = 4_0.75K,1%,0402,1_16W_1: CLABCONF0: DNP
R212 R297 = 33R,5%,0402,1_16W: CLABCONF0: DNP
R302 = 0R,_0402_0_7: CLABCONF0: DNP; P/N: 161C00005S
R303 = 0R,_0402_0_1: CLABCONF0: =SB-UCMIMX8PLUS; P/N: 161C00005S
R313 = 10K,1%,0402,1_16W_9: CLABCONF0: =SB-UCMIMX8PLUS
R314 = 10K,1%,0402,1_16W_10: CLABCONF0: =SB-UCMIMX8PLUS
R90 R315 = 10K,1%,0402,1_16W_2: CLABCONF0: =SB-UCMIMX8PLUS
R129 R316 = 10K,1%,0402,1_16W_5: CLABCONF0: =SB-UCMIMX8PLUS
R79 R317 = 0R,_0402_0_2: CLABCONF0: =SB-UCMIMX8PLUS; P/N: 161C00005S
R94 R329 = 10K,1%,0402,1_16W_7: CLABCONF0: =SB-UCMIMX8PLUS
R354 = 0R,_0402_0_3: CLABCONF0: =SB-UCMIMX8PLUS; P/N: 161C00005S
R355 = 0R,_0402_0_8: CLABCONF0: =SB-UCMIMX8PLUS; P/N: 161C00005S
R356 = 0R,_0402_0_6: CLABCONF0: =SB-UCMIMX8PLUS; P/N: 161C00005S
R275 R358 = 0R,_0402_0: CLABCONF0: =SB-UCMIMX8PLUS; P/N: 161C00005S
R360 = 0R,_0402_0_4: CLABCONF0: =SB-UCMIMX8PLUS; P/N: 161C00005S
R361 = 0R,_0402_0_5: CLABCONF0: =SB-UCMIMX8PLUS; P/N: 161C00005S
U46 U57 = 7SZ32_OR_sgl_SC70: CLABCONF0: =SB-UCMIMX8PLUS
U63 U64 = MAX14998ETOT: CLABCONF0: =SB-UCMIMX8PLUS
C84 = 100nF,_10V,_X7R,_10%,_0402_17: CLABCONF0: =SB-UCMIMX8PLUS
C86 = 100nF,_10V,_X7R,_10%,_0402_30: CLABCONF0: =SB-UCMIMX8PLUS
C87 = 100nF,_10V,_X7R,_10%,_0402_25: CLABCONF0: =SB-UCMIMX8PLUS
C88 = 100nF,_10V,_X7R,_10%,_0402_26: CLABCONF0: =SB-UCMIMX8PLUS
C100 = 100nF,_10V,_X7R,_10%,_0402_23: CLABCONF0: =SB-UCMIMX8PLUS
C104 = 100nF,_10V,_X7R,_10%,_0402_22: CLABCONF0: =SB-UCMIMX8PLUS
C161 = Cap.,_47uF,_16V,_X5R_1: CLABCONF0: =SB-UCMIMX8PLUS
C162 = Cap.,_47uF,_16V,_X5R_2: CLABCONF0: =SB-UCMIMX8PLUS
C163 = Cap.,_47uF,_16V,_X5R: CLABCONF0: =SB-UCMIMX8PLUS
C171 = 100nF,_10V,_X7R,_10%,_0402_29: CLABCONF0: =SB-UCMIMX8PLUS
C232 = 220nF,_25V,_X7R,_10%,_0402_2: CLABCONF0: =SB-UCMIMX8PLUS
C233 = 220nF,_25V,_X7R,_10%,_0402_1: CLABCONF0: =SB-UCMIMX8PLUS
C234 = 220nF,_25V,_X7R,_10%,_0402_3: CLABCONF0: =SB-UCMIMX8PLUS
C235 = 220nF,_25V,_X7R,_10%,_0402: CLABCONF0: =SB-UCMIMX8PLUS
C834 = 100nF,_10V,_X7R,_10%,_0402_14: CLABCONF0: =SB-UCMIMX8PLUS
C835 = 100nF,_10V,_X7R,_10%,_0402_16: CLABCONF0: =SB-UCMIMX8PLUS
C836 = 100nF,_10V,_X7R,_10%,_0402_19: CLABCONF0: =SB-UCMIMX8PLUS
C838 = 100nF,_10V,_X7R,_10%,_0402_21: CLABCONF0: =SB-UCMIMX8PLUS
C839 = 100nF,_10V,_X7R,_10%,_0402_27: CLABCONF0: =SB-UCMIMX8PLUS
C845 = 100nF,_10V,_X7R,_10%,_0402_15: CLABCONF0: =SB-UCMIMX8PLUS
C853 = 100nF,_10V,_X7R,_10%,_0402_18: CLABCONF0: =SB-UCMIMX8PLUS
C854 = 100nF,_10V,_X7R,_10%,_0402_20: CLABCONF0: =SB-UCMIMX8PLUS
C855 = 100nF,_10V,_X7R,_10%,_0402_28: CLABCONF0: =SB-UCMIMX8PLUS
C856 = 10uF_10V_20%_0402: CLABCONF0: =SB-UCMIMX8PLUS; P/N: 151C10610S
C858 = 10uF_10V_20%_0402_1: CLABCONF0: =SB-UCMIMX8PLUS; P/N: 151C10610S
C859 = 100nF,_10V,_X7R,_10%,_0402_24: CLABCONF0: =SB-UCMIMX8PLUS
C868 = 100nF_0402_25V_1: CLABCONF0: =SB-UCMIMX8PLUS
C869 = 100nF_0402_25V_3: CLABCONF0: =SB-UCMIMX8PLUS
C870 = 100nF_0402_25V_2: CLABCONF0: =SB-UCMIMX8PLUS
C871 = 100nF_0402_25V: CLABCONF0: =SB-UCMIMX8PLUS
D13 = Diode_,TVS_,15V,1500W_0: CLABCONF0: =SB-UCMIMX8PLUS; P/N: 132D00150S
DS17-DS19 DS22 = LED-RED_1206_0: CLABCONF0: =SB-UCMIMX8PLUS; P/N: 139A10260S
DS20 DS21 DS23 = LED-RED_0: CLABCONF0: =SB-UCMIMX8PLUS
DS24 = LED-GREEN_1206_3: CLABCONF0: =SB-UCMIMX8PLUS; P/N: 139A10010S
E16 = HDR_1x2_100MIL_TH_JUMPER_1: CLABCONF0: =SB-UCMIMX8PLUS
FB4 = Ferrite_bead_,_120_Ohm@3A_1: CLABCONF0: =SB-UCMIMX8PLUS; P/N: 147D30000S
FB5 = Ferrite_bead_,_120_Ohm@3A_2: CLABCONF0: =SB-UCMIMX8PLUS; P/N: 147D30000S
FB6 = Ferrite_bead_,_120_Ohm@3A: CLABCONF0: =SB-UCMIMX8PLUS; P/N: 147D30000S
FB7 = Ferrite_bead_,_120_Ohm@3A_3: CLABCONF0: =SB-UCMIMX8PLUS; P/N: 147D30000S
J9-J12 = FAKRA-RF-Male-50Ohm-Z_4: CLABCONF0: =SB-UCMIMX8PLUS
L47 L50 L53 L56 = IND_100uH_0_0.86A: CLABCONF0: =SB-UCMIMX8PLUS
L48 L51 L54 L57 = IND_6.8uH_3.5A: CLABCONF0: =SB-UCMIMX8PLUS; P/N: 147A6R801S
L49 L52 L55 L58 = IND_6.8uH_3_2.5A: CLABCONF0: =SB-UCMIMX8PLUS; P/N: 147AR3301S
P8 = TerminalBlk_0: CLABCONF0: = SB-UCMIMX8PLUS; Group: Always
P17 = Conn.,_W2B,_Header,_2x1,_1.25mm: CLABCONF0: =SB-UCMIMX8PLUS
R89 = 0R,_0402_1_6: CLABCONF0: DNP
R91 = 10K,1%,0402,1_16W_4: CLABCONF0: DNP
R92 = 4_0.75K,1%,0402,1_16W_2: CLABCONF0: =SB-UCMIMX8PLUS
R93 = 4_0.75K,1%,0402,1_16W: CLABCONF0: =SB-UCMIMX8PLUS
R95 = 348R,1%,0402,1_16W_2: CLABCONF0: =SB-UCMIMX8PLUS; P/N: 161C49R91S
R96 = 348R,1%,0402,1_16W: CLABCONF0: =SB-UCMIMX8PLUS; P/N: 161C49R91S
R97 = 348R,1%,0402,1_16W_3: CLABCONF0: =SB-UCMIMX8PLUS; P/N: 161C49R91S
R98 = 348R,1%,0402,1_16W_1: CLABCONF0: =SB-UCMIMX8PLUS; P/N: 161C49R91S
R154 = 100K,_1%,_0402,_1_16W: CLABCONF0: =SB-UCMIMX8PLUS
R213 = 4_0.75K,1%,0402,1_16W_12: CLABCONF0: DNP
R276 = 0R,_0402_0_1: CLABCONF0: DNP; P/N: 161C00005S
R277 = 4_0.75K,1%,0402,1_16W_14: CLABCONF0: DNP
R278 = 4_0.75K,1%,0402,1_16W_16: CLABCONF0: =SB-UCMIMX8PLUS
R279 = 4_0.75K,1%,0402,1_16W_1: CLABCONF0: =SB-UCMIMX8PLUS
R280 = 4_0.75K,1%,0402,1_16W_6: CLABCONF0: DNP
R281 = 4_0.75K,1%,0402,1_16W_9: CLABCONF0: =SB-UCMIMX8PLUS
R282 = 4_0.75K,1%,0402,1_16W_11: CLABCONF0: DNP
R283 = 4_0.75K,1%,0402,1_16W_15: CLABCONF0: DNP
R284 = 4_0.75K,1%,0402,1_16W_3: CLABCONF0: =SB-UCMIMX8PLUS
R285 = 4_0.75K,1%,0402,1_16W_13: CLABCONF0: =SB-UCMIMX8PLUS
R286 = 4_0.75K,1%,0402,1_16W_5: CLABCONF0: DNP
R287 = 4_0.75K,1%,0402,1_16W_10: CLABCONF0: DNP
R288 = 4_0.75K,1%,0402,1_16W_8: CLABCONF0: DNP
R289 = 4_0.75K,1%,0402,1_16W_7: CLABCONF0: DNP
R290 = 4_0.75K,1%,0402,1_16W_4: CLABCONF0: DNP
R291 = 2.2K,5%,0402.1_16W_6: CLABCONF0: =SB-UCMIMX8PLUS
R292 = 0R,_0402_1_12: CLABCONF0: =SB-UCMIMX8PLUS
R293 = 0R,_0402_1_7: CLABCONF0: DNP
R294 = 0R,_0402_1_9: CLABCONF0: DNP
R296 = 0R,_0402_1_8: CLABCONF0: =SB-UCMIMX8PLUS
R298 = 0R,_0402_1_10: CLABCONF0: =SB-UCMIMX8PLUS
R300 = 0R,_0402_1_13: CLABCONF0: =SB-UCMIMX8PLUS
R304-R310 = 150R,1%,0402,1_16W_0: CLABCONF0: =SB-UCMIMX8PLUS
R311 = 47K,_0402: CLABCONF0: =SB-UCMIMX8PLUS; P/N: 161D56001S
R312 = 0R,_0402_1_1: CLABCONF0: DNP
R326 = 0R,_0402_1_11: CLABCONF0: =SB-UCMIMX8PLUS
R359 = 0R,_0402_1_14: CLABCONF0: =SB-UCMIMX8PLUS
R898 = 2.2K,5%,0402.1_16W_15: CLABCONF0: =SB-UCMIMX8PLUS
R899 = 2.2K,5%,0402.1_16W_3: CLABCONF0: DNP
R900 = 2.2K,5%,0402.1_16W_5: CLABCONF0: =SB-UCMIMX8PLUS
R901 = 2.2K,5%,0402.1_16W_4: CLABCONF0: =SB-UCMIMX8PLUS
R902 = 2.2K,5%,0402.1_16W_10: CLABCONF0: =SB-UCMIMX8PLUS
R903 = 2.2K,5%,0402.1_16W_1: CLABCONF0: =SB-UCMIMX8PLUS; P/N: 161C20011S
R904 = 2.2K,5%,0402.1_16W_14: CLABCONF0: =SB-UCMIMX8PLUS; P/N: 161C20011S
R905 = 2.2K,5%,0402.1_16W_16: CLABCONF0: =SB-UCMIMX8PLUS; P/N: 161C20011S
R906 = 2.2K,5%,0402.1_16W_9: CLABCONF0: =SB-UCMIMX8PLUS; P/N: 161C20011S
R907 = 2.2K,5%,0402.1_16W_17: CLABCONF0: =SB-UCMIMX8PLUS; P/N: 161C20011S
R908 = 2.2K,5%,0402.1_16W: CLABCONF0: =SB-UCMIMX8PLUS; P/N: 161C20011S
R909 = 2.2K,5%,0402.1_16W_7: CLABCONF0: =SB-UCMIMX8PLUS; P/N: 161C20011S
R910 = 2.2K,5%,0402.1_16W_11: CLABCONF0: =SB-UCMIMX8PLUS; P/N: 161C20011S
R911 = 2.2K,5%,0402.1_16W_13: CLABCONF0: =SB-UCMIMX8PLUS; P/N: 161C20011S
R912 = 2.2K,5%,0402.1_16W_2: CLABCONF0: =SB-UCMIMX8PLUS; P/N: 161C20011S
R913 = 2.2K,5%,0402.1_16W_12: CLABCONF0: =SB-UCMIMX8PLUS; P/N: 161C20011S
R914 = 2.2K,5%,0402.1_16W_8: CLABCONF0: =SB-UCMIMX8PLUS; P/N: 161C20011S
U45 U50-U55 = MicroGate_NC7SZ57,Univ_Gate: CLABCONF0: =SB-UCMIMX8PLUS; P/N: 106C20580S
U47 = MAXIM_MAX9286: CLABCONF0: =SB-UCMIMX8PLUS
U48 = MicroGate_NC7SZ57,Univ_Gate: CLABCONF0: =SB-UCMIMX8PLUS; P/N: 106C20570S

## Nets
1V8_B_FLASH_OUT: P47.29(FLASH) R274.1 R294.1
1V8_B_RST: P47.21(RESET) R128.2 R239.1 R365.1
1V8_B_TRG: P47.12(TRIGGER) R269.1 R293.1
1V8_PER: C842.1 C850.1 C874.1 C875.1 FB4.1 FB5.1 FB6.1 FB7.1 P47.3(VCC_1P8) P48.3(VCC_1P8) R89.2 R94.1 R101.2 R275.1 R303.1 U48.3(I0) U48.5(VCC) ; also on sheet 10 12 13 15
1V8_PWR_DWN_B: P47.6(PWDN) R129.2 R273.1 U48.6(I2)
3V3_PER: C1.1 C27.1 C65.2 C87.1 C101.1 C104.2 C105.2 C159.2 C160.2 C164.1 C169.1 C170.2 C171.2 C174.2 C175.2 C191.1 C202.1 C853.1 C872.1 C873.1 C876.1 C877.1 C878.1 C879.1 C880.1 C881.1 D24.2(ANODE) E16.1 E18.1 P5.3 P11.38 P11.39 P47.1(VCC1_3P3) P47.2(VCC2_3P3) P48.1(VCC1_3P3) P48.2(VCC2_3P3) P49.22 Q24.2(G1) Q24.5(G2) R3.2 R54.1 R56.1 R60.1 R62.1 R88.1 R100.1 R152.2 R153.2 R265.1 R266.1 R270.1 R276.1 R302.1 U9.3(VCCA) U12.7(VCCB) U13.7(VCCB) U17.7(VCCB) U33.5(VBUS) U44.7(VCCB) U63.1(VDD) U63.6(VDD_1) U63.13(VDD_2) U63.26(VDD_3) U64.1(VDD) U64.6(VDD_1) U64.13(VDD_2) U64.26(VDD_3) ; also on sheet 6 8 9 10 11 12 13 14 15
5V0_PER: F4.2 R73.1 ; also on sheet 8 10 13
AVDD_DS: C832.1 C833.1 C834.1 C835.1 C836.1 C848.1 FB4.2 U47.10(AVDD) U47.17(AVDD) U47.26(AVDD) U47.45(AVDD) U47.54(AVDD)
DVDD_DS: C838.1 C839.1 C840.1 C841.1 C847.1 FB5.2 U47.5(DVDD) U47.9(DVDD) U47.20(DVDD) U47.51(DVDD)
GND: C1.2 C27.2 C55.2 C56.2 C57.2 C58.2 C64.1 C65.1 C67.1 C82.1 C83.2 C84.2 C86.2 C87.2 C88.2 C100.2 C101.2 C102.2 C104.1 C105.1 C106.2 C107.2 C159.1 C160.1 C161.2 C162.2 C163.2 C164.2 C165.2 C167.2 C168.2 C169.2 C170.1 C171.1 C174.1 C175.1 C191.2 C202.2 C359.2 C832.2 C833.2 C834.2 C835.2 C836.2 C838.2 C839.2 C840.2 C841.2 C842.2 C843.2 C844.2 C845.2 C846.2 C847.2 C848.2 C849.2 C850.2 C851.2 C852.2 C853.2 C856.1 C857.2 C858.1 C859.2 C872.2 C873.2 C874.2 C875.2 C876.2 C877.2 C878.2 C879.2 C880.2 C881.2 D13.2 DS24.CATHODE J9.2(GND) J9.3(GND) J9.4(GND) J9.5(GND) J10.2(GND) J10.3(GND) J10.4(GND) J10.5(GND) J11.2(GND) J11.3(GND) J11.4(GND) J11.5(GND) J12.2(GND) J12.3(GND) J12.4(GND) J12.5(GND) L1.5(GND) L1.6(GND) L2.5(GND) L2.6(GND) L7.5(GND) L7.6(GND) L12.5(GND) L12.6(GND) L13.5(GND) L13.6(GND) L25.5(GND) L25.6(GND) L27.5(GND) L27.6(GND) L28.5(GND) L28.6(GND) L29.5(GND) L29.6(GND) L30.5(GND) L30.6(GND) OSC3.2(GND) OSC4.2(GND) P5.1 P5.8 P5.9 P5.10 P8.2 P11.11 P11.16 P11.19 P11.22 P11.25 P11.28 P11.31 P11.34 P14.2(D2_Shield) P14.5(D1_Shield) P14.8(D0_Shield) P14.11(CK_Shield) P14.17(GND) P14.20(SHELL1) P14.21(SHELL2) P17.M1 P17.M2 P47.4(GND1) P47.5(GND2) P47.9(GND3) P47.14(GND4) P47.17(GND5) P47.18(GND6) P47.22(GND7) P47.26(GND8) P47.SH1 P47.SH2 P47.SH3 P47.SH4 P47.SH5 P47.SH6 P47.SH7 P47.SH8 P47.SH9 P47.SH10 P47.SH11 P47.SH12 P47.SH13 P47.SH14 P47.SH15 P47.SH16 P47.SH17 P47.SH18 P47.SH19 P48.4(GND1) P48.5(GND2) P48.9(GND3) P48.14(GND4) P48.17(GND5) P48.18(GND6) P48.22(GND7) P48.26(GND8) P48.SH1 P48.SH2 P48.SH3 P48.SH4 P48.SH5 P48.SH6 P48.SH7 P48.SH8 P48.SH9 P48.SH10 P48.SH11 P48.SH12 P48.SH13 P48.SH14 P48.SH15 P48.SH16 P48.SH17 P48.SH18 P48.SH19 P49.1 P49.4 P49.7 P49.10 P49.13 P49.16 P49.19 P49.NC1 P49.NC2 R55.2 R59.2 R61.2 R63.2 R64.2 R82.1 R87.1 R91.1 R95.2 R96.2 R97.2 R98.2 R103.1 R128.1 R129.1 R154.2 R256.1 R278.2 R279.2 R282.2 R283.2 R285.2 R286.2 R288.2 R289.2 R313.1 R314.1 R316.1 R328.1 R341.1 R884.2 U5.4(GND) U9.2(GND) U12.2(GND) U13.2(GND) U17.2(GND) U33.2(GND) U38.2(GND) U44.2(GND) U45.1(I1) U45.2(GND) U45.3(I0) U46.3(GND) U47.57(EP) U48.2(GND) U50.1(I1) U50.2(GND) U50.3(I0) U51.1(I1) U51.2(GND) U51.3(I0) U52.1(I1) U52.2(GND) U52.3(I0) U53.1(I1) U53.2(GND) U53.3(I0) U54.2(GND) U54.3(I0) U55.1(I1) U55.2(GND) U55.3(I0) U57.3(GND) U63.Tpad U64.Tpad ; also on sheet 6 7 8 9 10 11 12 13 14 15
VDD_3P3_CN: D24.1(CATHODE) R264.2
VDDIO_DS: C843.1 C844.1 C845.1 C849.1 FB6.2 R213.1 R277.1 R280.1 R281.1 R284.1 R287.1 R290.1 R291.1 R304.2 R305.2 R306.2 R307.2 R308.2 R309.2 R310.2 R898.1 R899.1 R900.1 R901.1 R902.1 U45.5(VCC) U47.3(IOVDD) U47.22(IOVDD) U47.49(IOVDD) U50.5(VCC) U51.5(VCC) U52.5(VCC) U53.5(VCC) U54.1(I1) U54.5(VCC) U55.5(VCC)
CN_DS_MONN: C854.2 P17.1
CN_DS_MONP: C855.2 P17.2
CN_LVDS_DISP_RESET: C64.2 P11.36 R3.1 R151.2
CS2_P1_SCL: P47.7(I2C_SCL) R359.1
CS2_P1_SDA: P47.8(I2C_SDA) R326.1
CSI1_B_FLASH_OUT: R339.2 U13.1(B2) ; also on sheet 10
CSI1_B_FLASH_OUT_1V8: P48.29(FLASH) R301.1
CSI1_B_RST: R340.2 ; also on sheet 10
CSI1_B_RST_1V8: P48.21(RESET) R340.1 R341.2
CSI1_B_TRG: U13.8(B1) ; also on sheet 10
CSI1_B_TRG_1V8: P48.12(TRIGGER) R299.1
CSI1_GPIO_1V8_ENABLE: R313.2 R327.1 U13.6(OE)
CSI1_I2C_1V8_ENABLE: R314.2 R329.1 U44.6(OE)
CSI1_MCLK_B: P48.13(RSVD1) R297.2
CSI1_MCLK_VCC_B: C165.1 OSC4.4(VCC) R100.2 R101.1 R102.1
CSI1_P22_CKN: P49.8 U63.39(NC1-)
CSI1_P22_CKP: P49.9 U63.40(NC1+)
CSI1_P22_DN0: P49.2 U63.37(NC2-)
CSI1_P22_DN1: P49.5 U63.35(NC3-)
CSI1_P22_DN2: P49.11 U63.24(NC4-)
CSI1_P22_DN3: P49.14 U63.41(NC0-)
CSI1_P22_DP0: P49.3 U63.38(NC2+)
CSI1_P22_DP1: P49.6 U63.36(NC3+)
CSI1_P22_DP2: P49.12 U63.25(NC4+)
CSI1_P22_DP3: P49.15 U63.42(NC0+)
CSI1_P22_I2C_SCL: P49.20 R354.2
CSI1_P22_I2C_SDA: P49.21 R355.2
CSI1_P30_CKN: P48.24(MIPI_CLK_N) U63.31(NO1-)
CSI1_P30_CKP: P48.25(MIPI_CLK_P) U63.32(NO1+)
CSI1_P30_DN0: P48.19(MIPI_D0_N) U63.29(NO2-)
CSI1_P30_DN1: P48.15(MIPI_D1_N) U63.27(NO3-)
CSI1_P30_DN2: P48.10(MIPI_D2_N) U63.20(NO4-)
CSI1_P30_DN3: P48.27(MIPI_D3_N) U63.33(NO0-)
CSI1_P30_DP0: P48.20(MIPI_D0_P) U63.30(NO2+)
CSI1_P30_DP1: P48.16(MIPI_D1_P) U63.28(NO3+)
CSI1_P30_DP2: P48.11(MIPI_D2_P) U63.21(NO4+)
CSI1_P30_DP3: P48.28(MIPI_D3_P) U63.34(NO0+)
CSI1_PWR_DWN_B: R315.2 R317.1 ; also on sheet 10
CSI1_PWR_DWN_B_1V8: P48.6(PWDN) R315.1 R316.2
CSI1_SELECTOR: E18.2 R327.2 R328.2 R329.2 U63.16(SEL1) U63.17(SEL2)
CSI2_B_FLASH_OUT: U12.1(B2) ; also on sheet 10
CSI2_B_RST: R239.2 ; also on sheet 10
CSI2_B_TRG: U12.8(B1) ; also on sheet 10
CSI2_DS_CKN: U47.35(CLK-) U64.31(NO1-)
CSI2_DS_CKP: U47.36(CLK+) U64.32(NO1+)
CSI2_DS_DN0: U47.39(DOUT0-) U64.29(NO2-)
CSI2_DS_DN1: U47.37(DOUT1-) U64.27(NO3-)
CSI2_DS_DN2: U47.33(DOUT2-) U64.20(NO4-)
CSI2_DS_DN3: U47.31(DOUT3-) U64.33(NO0-)
CSI2_DS_DP0: U47.40(DOUT0+) U64.30(NO2+)
CSI2_DS_DP1: U47.38(DOUT1+) U64.28(NO3+)
CSI2_DS_DP2: U47.34(DOUT2+) U64.21(NO4+)
CSI2_DS_DP3: U47.32(DOUT3+) U64.34(NO0+)
CSI2_LSGPIO_OE: R79.2 R87.2 U12.6(OE)
CSI2_MCLK_B: P47.13(RSVD1) R212.2
CSI2_MCLK_VCC_B: C88.1 OSC3.4(VCC) R88.2 R89.1 R90.1
CSI2_P1_CKN: P47.24(MIPI_CLK_N) U64.39(NC1-)
CSI2_P1_CKP: P47.25(MIPI_CLK_P) U64.40(NC1+)
CSI2_P1_DN0: P47.19(MIPI_D0_N) U64.37(NC2-)
CSI2_P1_DN1: P47.15(MIPI_D1_N) U64.35(NC3-)
CSI2_P1_DN2: P47.10(MIPI_D2_N) U64.24(NC4-)
CSI2_P1_DN3: P47.27(MIPI_D3_N) U64.41(NC0-)
CSI2_P1_DP0: P47.20(MIPI_D0_P) U64.38(NC2+)
CSI2_P1_DP1: P47.16(MIPI_D1_P) U64.36(NC3+)
CSI2_P1_DP2: P47.11(MIPI_D2_P) U64.25(NC4+)
CSI2_P1_DP3: P47.28(MIPI_D3_P) U64.42(NC0+)
CSI2_PWR_DWN_B: R273.2 ; also on sheet 10
CSI2_SCCB_EN: C102.1 R94.2 U17.6(OE)
CSI2_SELECTOR: E16.2 R82.2 U48.1(I1) U64.16(SEL1) U64.17(SEL2)
DS_ADD0: R213.2 R278.1 U47.13(ADD0)
DS_ADD1: R277.2 R279.1 U47.14(ADD1)
DS_BWS: R288.1 R290.2 U47.18(BWS)
DS_CCBSYS: R296.2 R898.2 U50.6(I2)
DS_CR0: C868.2 R95.1
DS_CR1: C870.2 R97.1
DS_CR2: C869.2 R96.1
DS_CR3: C871.2 R98.1
DS_CXTP: R284.2 R286.1 U47.25(CX/TP)
DS_DISABLE: R292.2 R312.1 U48.4(Y)
DS_EERB: R900.2 U47.29(ERR#) U52.6(I2)
DS_FSYNC: R295.1 R365.2 R899.2 U51.6(I2)
DS_GPIO0: R293.2 U47.1(GPIO0)
DS_GPIO1: R294.2 U47.2(GPIO1)
DS_HIM: R289.1 R291.2 U47.24(HIM)
DS_I2CSEL: R281.2 R283.1 U47.6(I2CSEL)
DS_IN0N: C868.1 U47.15(IN0-)
DS_IN0P: C232.2 U47.16(IN0+)
DS_IN1N: C870.1 U47.27(IN1-)
DS_IN1P: C233.2 U47.28(IN1+)
DS_IN2N: C869.1 U47.43(IN2-)
DS_IN2P: C234.2 U47.44(IN2+)
DS_IN3N: C871.1 U47.55(IN3-)
DS_IN3P: C235.2 U47.56(IN3+)
DS_LFLT: R901.2 U47.48(LFLT#) U53.6(I2)
DS_LMO: R902.2 U47.50(LMO#) U55.6(I2)
DS_LOCK: U47.42(LOCK) U54.6(I2)
DS_MONN: C854.1 U47.11(MON-)
DS_MONP: C855.1 U47.12(MON+)
DS_MS: R285.1 R287.2 U47.46(MS)
DS_PWDNB: R280.2 R282.1 R292.1 U45.6(I2) U47.47(PWDN#)
DS_R_CCBSYS: R296.1 U47.23(CCBSYS#)
DS_R_FSYNC: R295.2 U47.4(FRSYNC/GPI)
DS_SCL: R300.1 U47.8(TX/SCL)
DS_SDA: R298.1 U47.7(RX/SDA)
EARC_N: C358.2 L29.3 R171.2
EARC_N_HPD: C358.1 ; also on sheet 6
EARC_P: C360.2 L29.4
EARC_P_UTIL: C360.1 ; also on sheet 6
FPC22_17: P49.17 R317.2
FPC22_18: P49.18 R339.1
HDMI_5V_FL: C359.1 D23.2(ANODE) F4.1
HDMI_5VSCHT: C67.2 C82.2 D23.1(CATHODE) P14.18(+5V) R267.1 R268.1 R884.1 U9.7(VCCB) U38.1(IO1) U38.5(VBUS)
HDMI_CEC: D25.2(ANODE) Q24.4(S2) R152.1 ; also on sheet 6 10
HDMI_CEC_3P3: D25.1(CATHODE) P14.13(CE_Remote) Q24.3(D2) R264.1 U38.6(IO4)
HDMI_DDC_SCL: R266.2 U9.5(A1) ; also on sheet 6 10
HDMI_DDC_SDA: R265.2 U9.4(A2) ; also on sheet 6 10
HDMI_HPD: Q24.1(S1) R153.1 ; also on sheet 6 10
HDMI_HPD_5V: Q24.6(D1) R171.1 R256.2
HDMI_HPD_CN: L29.2 P14.19(HP_DET)
HDMI_TX0N: R351.2 ; also on sheet 6
HDMI_TX0P: R350.2 ; also on sheet 6
HDMI_TX1N: R349.2 ; also on sheet 6
HDMI_TX1P: R348.2 ; also on sheet 6
HDMI_TX2N: R345.2 ; also on sheet 6
HDMI_TX2P: R344.2 ; also on sheet 6
HDMI_TXCN: R353.2 ; also on sheet 6
HDMI_TXCP: R352.2 ; also on sheet 6
HDMI_UTILITY_CN: L29.1 P14.14(NC)
I2C5_3V3_SCL: R358.2 U44.1(B2)
I2C5_3V3_SDA: R356.2 U44.8(B1)
I2C5_SCL/SAI5_RXD0: R354.1 R358.1 ; also on sheet 6 10 11
I2C5_SCL_1V8: R105.2 R360.1 U44.4(A2)
I2C5_SDA/SAI5_MCLK: R355.1 R356.1 ; also on sheet 6 10 11
I2C5_SDA_1V8: R104.2 R361.1 U44.5(A1)
I2C6_SCL: P5.4 U17.1(B2) U33.1(IO1) ; also on sheet 10
I2C6_SCL_1V8: R93.2 R300.2 R359.2 U17.4(A2)
I2C6_SDA: P5.5 U17.8(B1) U33.3(IO2) ; also on sheet 10
I2C6_SDA_1V8: R92.2 R298.2 R326.2 U17.5(A1)
LEDA_CCBSYS: DS18.ANODE R305.1
LEDA_ERRB: DS20.ANODE R307.1
LEDA_GPI: DS19.ANODE R306.1
LEDA_LFLT: DS21.ANODE R308.1
LEDA_LMO: DS23.ANODE R310.1
LEDA_LOCK: DS22.ANODE R309.1
LEDA_PWDNB: DS17.ANODE R304.1
LEDC_CCBSYS: DS18.CATHODE U50.4(Y)
LEDC_ERRB: DS20.CATHODE U52.4(Y)
LEDC_GPI: DS19.CATHODE U51.4(Y)
LEDC_LFLT: DS21.CATHODE U53.4(Y)
LEDC_LMO: DS23.CATHODE U55.4(Y)
LEDC_LOCK: DS22.CATHODE U54.4(Y)
LEDC_PWDNB: DS17.CATHODE U45.4(Y)
LVDS0_CLK_N: L13.3 ; also on sheet 6
LVDS0_CLK_P: L13.4 ; also on sheet 6
LVDS0_CLKN: L13.2 P11.24
LVDS0_CLKP: L13.1 P11.23
LVDS0_D0_N: L2.4 ; also on sheet 6
LVDS0_D0_P: L2.3 ; also on sheet 6
LVDS0_D1_N: L1.4 ; also on sheet 6
LVDS0_D1_P: L1.3 ; also on sheet 6
LVDS0_D2_N: L7.4 ; also on sheet 6
LVDS0_D2_P: L7.3 ; also on sheet 6
LVDS0_D3_N: L12.4 ; also on sheet 6
LVDS0_D3_P: L12.3 ; also on sheet 6
LVDS0_N0: L2.1 P11.33
LVDS0_N1: L1.1 P11.30
LVDS0_N2: L7.1 P11.27
LVDS0_N3: L12.1 P11.21
LVDS0_P0: L2.2 P11.32
LVDS0_P1: L1.2 P11.29
LVDS0_P2: L7.2 P11.26
LVDS0_P3: L12.2 P11.20
LVDS_COMP: C58.1 U5.5(COMP)
LVDS_DIMO: P11.14 TP4.1
LVDS_DISP_RESET: R151.1 ; also on sheet 10
LVDS_L_R: P11.8 R56.2 R59.1
LVDS_LED_EN: R52.2 R74.2 U5.2(CTRL)
LVDS_LED_N: R65.1 R66.1 R68.2 U5.6(FB)
LVDS_LED_NEG: C85.1 P11.9 P11.10 R68.1
LVDS_LED_P: C57.1 D11.CATHODE R67.2
LVDS_LED_POS: C85.2 P11.1 P11.2 R67.1
LVDS_RESET: R63.1 R65.2 R66.2
LVDS_SELB: P11.13 R62.2 R64.1
LVDS_STBYB: P11.35 R54.2 R55.1
LVDS_SW_PWR_IN: C55.1 C56.1 L9.1 R52.1 R73.2 U5.1(IN)
LVDS_TOUCH_RESET: P5.7 U33.6(IO4) ; also on sheet 10
LVDS_U_D: P11.7 R60.2 R61.1
LVDS_WLD_SW: D11.ANODE L9.2 U5.3(SW)
MAVDD_DS: C846.1 C851.1 C852.1 FB7.2 U47.30(MAVDD) U47.41(MAVDD)
MIPI_CSI1_CLK_N: U63.5(COM1-) ; also on sheet 6
MIPI_CSI1_CLK_P: U63.4(COM1+) ; also on sheet 6
MIPI_CSI1_D0_N: U63.8(COM2-) ; also on sheet 6
MIPI_CSI1_D0_P: U63.7(COM2+) ; also on sheet 6
MIPI_CSI1_D1_N: U63.10(COM3-) ; also on sheet 6
MIPI_CSI1_D1_P: U63.9(COM3+) ; also on sheet 6
MIPI_CSI1_D2_N: U63.12(COM4-) ; also on sheet 6
MIPI_CSI1_D2_P: U63.11(COM4+) ; also on sheet 6
MIPI_CSI1_D3_N: U63.3(COM0-) ; also on sheet 6
MIPI_CSI1_D3_P: U63.2(COM0+) ; also on sheet 6
MIPI_CSI2_CLK_N: U64.5(COM1-) ; also on sheet 6
MIPI_CSI2_CLK_P: U64.4(COM1+) ; also on sheet 6
MIPI_CSI2_D0_N: U64.8(COM2-) ; also on sheet 6
MIPI_CSI2_D0_P: U64.7(COM2+) ; also on sheet 6
MIPI_CSI2_D1_N: U64.10(COM3-) ; also on sheet 6
MIPI_CSI2_D1_P: U64.9(COM3+) ; also on sheet 6
MIPI_CSI2_D2_N: U64.12(COM4-) ; also on sheet 6
MIPI_CSI2_D2_P: U64.11(COM4+) ; also on sheet 6
MIPI_CSI2_D3_N: U64.3(COM0-) ; also on sheet 6
MIPI_CSI2_D3_P: U64.2(COM0+) ; also on sheet 6
OE_DDC_LS: R270.2 U9.6(OE)
OSC3_EN: OSC3.1(EN) R90.2 R91.2 R312.2
OSC3_OUT: OSC3.3(OUT) U46.1(A) U46.2(B)
OSC4_EN: OSC4.1(EN) R102.2 R103.2
OSC4_OUT: OSC4.3(OUT) U57.1(A) U57.2(B)
P48_I2C_SCL: P48.7(I2C_SCL) R360.2
P48_I2C_SDA: P48.8(I2C_SDA) R361.2
PO_COAX_12V: C161.1 C856.2 C857.1 D13.1 E17.1 P8.1 R154.1 R311.2
PO_COAX_ALL: C162.1 C163.1 C858.2 C859.1 E17.2 L47.1 L50.1 L53.1 L56.1 R903.1 R906.1 R909.1 R912.1
PO_COAX_FAKRA0: C232.1 J9.1(C) L58.2 R914.2
PO_COAX_FAKRA1: C233.1 J10.1(C) L52.2 R908.2
PO_COAX_FAKRA2: C234.1 J11.1(C) L55.2 R911.2
PO_COAX_FAKRA3: C235.1 J12.1(C) L49.2 R905.2
PO_COAX_L0: L56.2 L57.1 R912.2 R913.1
PO_COAX_L1: L50.2 L51.1 R906.2 R907.1
PO_COAX_L2: L53.2 L54.1 R909.2 R910.1
PO_COAX_L3: L47.2 L48.1 R903.2 R904.1
PO_COAX_LL0: L57.2 L58.1 R913.2 R914.1
PO_COAX_LL1: L51.2 L52.1 R907.2 R908.1
PO_COAX_LL2: L54.2 L55.1 R910.2 R911.1
PO_COAX_LL3: L48.2 L49.1 R904.2 R905.1
PO_LED_A: DS24.ANODE R311.1
SPDIF_RX: R74.1 ; also on sheet 6 9
TMDS1_CLK_CN: L30.3 R353.1
TMDS1_CLK_CP: L30.4 R352.1
TMDS1_CLK_LN: L30.2 P14.12(CK-)
TMDS1_CLK_LP: L30.1 P14.10(CK+)
TMDS1_DCLK: P14.15(DDC_CLK) R267.2 U9.8(B1) U38.4(IO3)
TMDS1_DDAT: P14.16(DDC_DATA) R268.2 U9.1(B2) U38.3(IO2)
TMDS1_TX0_CN: L28.3 R351.1
TMDS1_TX0_CP: L28.4 R350.1
TMDS1_TX0_LN: L28.2 P14.9(D0-)
TMDS1_TX0_LP: L28.1 P14.7(D0+)
TMDS1_TX1_CN: L25.3 R349.1
TMDS1_TX1_CP: L25.4 R348.1
TMDS1_TX1_LN: L25.2 P14.6(D1-)
TMDS1_TX1_LP: L25.1 P14.4(D1+)
TMDS1_TX2_CN: L27.3 R345.1
TMDS1_TX2_CP: L27.4 R344.1
TMDS1_TX2_LN: L27.2 P14.3(D2-)
TMDS1_TX2_LP: L27.1 P14.1(D2+)
U12_A2: R269.2 U12.5(A1)
U12_A4: R274.2 U12.4(A2)
U13_A1: R299.2 U13.5(A1)
U13_A2: R301.2 U13.4(A2)
U46_4: R212.1 U46.4(A+B)
U57_4: R297.1 U57.4(A+B)
USB1_TYPEC_EN_B/SD2_WP: P5.6 U33.4(IO3) ; also on sheet 6
VIO_CAMERA_CSI1: C106.1 C107.1 C167.1 C168.1 R104.1 R105.1 R302.2 R303.2 U13.3(VCCA) U44.3(VCCA) U57.5(VCC)
VIO_CAMERA_CSI2: C83.1 C84.1 C86.1 C100.1 R79.1 R92.1 R93.1 R275.2 R276.2 U12.3(VCCA) U17.3(VCCA) U46.5(VCC)

Not connected (* = marked no-connect by the designer): P5 2*; P11 3* 4* 5* 6* 12* 15* 17* 18* 37* 40*; P47 23(RSVD2)* 30(RSVD3)*; P48 23(RSVD2)* 30(RSVD3)*; U47 19(LMN0)* 21(LMN1)* 52(LMN2)* 53(LMN3)*; U63 14(COM5+)* 15(COM5-)* 18(NO5-)* 19(NO5+)* 22(NC5-)* 23(NC5+)*; U64 14(COM5+)* 15(COM5-)* 18(NO5-)* 19(NO5+)* 22(NC5-)* 23(NC5+)*

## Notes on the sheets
sheet 1
- MIPI-CSI2 Connectors
- 30 pin Connector for
  e-CAM130_iMX8M
- SILKSCREEN:
  MIPI-CSI2 (30-pin, 1.8V)
- DNP
- DNP
- SILKSCREEN: Enable GMSL DeSer
- DNP
- Provision to disable oscillator
  if GMSL deserializer has been chosen
- # 100-Ohm diff pairs
- OE VCCA
  domain
- DNP
- GMSL Power on Coax 12V
- GMSL Coax Connectors (FAKRA)
- SILKSCREEN: Enable PoC
- # 100-Ohm diff pairs
- # 100-Ohm diff pairs
- GMSL Deserializer (MAX9286)
- SILKSCREEN:
  | (+) | PoC | (-) |
- AND
- # 100-Ohm diff pairs
- SILKSCREEN:
  PoC active
- GMSL Power
- DNP
- DNP
- GMSL Status LEDs
- XOR
- XOR
- GMSL Strap Jumpers
- Default Settings
- SILKSCREEN: PWDNB
- SILKSCREEN: CCBSYS
- DS_CXTP
- DS_MS
- DS_BWS
- DS_HIM
- DS_ADD0
- DS_ADD1
- DS_PWDNB
- DS_I2CSEL
- XOR
- DNP
- XOR
- # 100-Ohm diff pairs
- HIGH
- LOW
- OPEN
- HIGH
- LOW
- LOW
- OPEN
- HIGH
- SILKSCREEN: GPI
- SILKSCREEN: LOCK
- XOR
- XOR
- DNP
- DNP
- DNP
- DNP
- DNP
- SILKSCREEN: ERRB
- SILKSCREEN: LMO
- XOR
- DNP
- DNP
- DNP
- DNP
- DNP
- SILKSCREEN: LFLT
sheet 2
- MIPI-CSI1 Connectors
- 22-pin Connector for RPi cameras
  Four MIPI-CSI lanes connected
- SILKSCREEN:
  MIPI-CSI1 (22-pin, 3.3V)
- # 100-Ohm diff pairs
- SILKSCREEN:
  Enable 30-pin, 1.8V connector
- # 100-Ohm diff pairs
- R327,R313 - 3.3->1.8 Divider
- OE VCCA
  domain
- SILKSCREEN:
  MIPI-CSI1 (30-pin, 1.8V)
- DNP
- DNP
- R329,R314 - 3.3->1.8 Divider
- # 100-Ohm diff pairs
- 30 pin Connector for e-CAM130_iMX8M
  (e-con System)
- DNP
- DNP
- DNP
sheet 3
- HDMI connector with eARC
- # 100-Ohm diff pairs
- # 100-Ohm diff pairs
- # 100-Ohm diff pairs
- SILKSCREEN:
  HDMI 2.0 (eARC)
- eARC ESD and HPD DC Filter
- # 100-Ohm diff pairs
- DDC Level Shifter
- HPD and CEC Level Shifter
sheet 4
- LVDS connector
- LCD back-light power
- DNP
- DNP
- SPDIF_RX = PWM2_OUT
- # 100-Ohm diff pairs
- # 100-Ohm diff pairs
- DNP
- DNP
- DNP
- SILKSCREEN:
  LVDS LCD
- DNP
- LVDS Touch-panel connector
- SD2_WP = GPIO2_20
- SILKSCREEN:
  LVDS Touch Ctl.
- Pinout of J5 reversed
   to FPC
- GT911 supports two I2C slave
  addresses: 0xBA/0xBB and 0x28/0x29.
  The host can select the address by
  changing the status of Reset and INT
  pins during the power-on
  initialization phase, refer:
  139D10090 Data Sheet, page 16
sheet 5
- SB-UCM-iMX8PLUS
- BOARD REVISION: 1.1
- Attention:
  BOARD REVISION 1.1 requires
  Compulsory rework described on page 13
- Page
- Description
- 01
- Block Diagram
- 02
- Carrier-board interface
- 03
- RJ-45 Ethernet connector
- 04
- USB3.0, Type-C, Host
- 05
- Audio Codec
- 06
- JTAG, CAN, GPIO Exp., Misc.
- 07
- MIPI-DSI LCD
- 08
- LVDS LCD
- 09
- HDMI, eARC
- 10
- MIPI-CSI1 Connectors
- 11
- MIPI-CSI2 Connector, GMSL DeSer
- 12
- M.2 Key B, PCIe, USB3
- 13
- Power
- 14
- UART, RS232, SD, EEPROM
- 15
- Mechanical
- SILKSCREEN:
  CompuLab
  SB-UCMIMX8PLUS Rev 1.1
  188C03841
